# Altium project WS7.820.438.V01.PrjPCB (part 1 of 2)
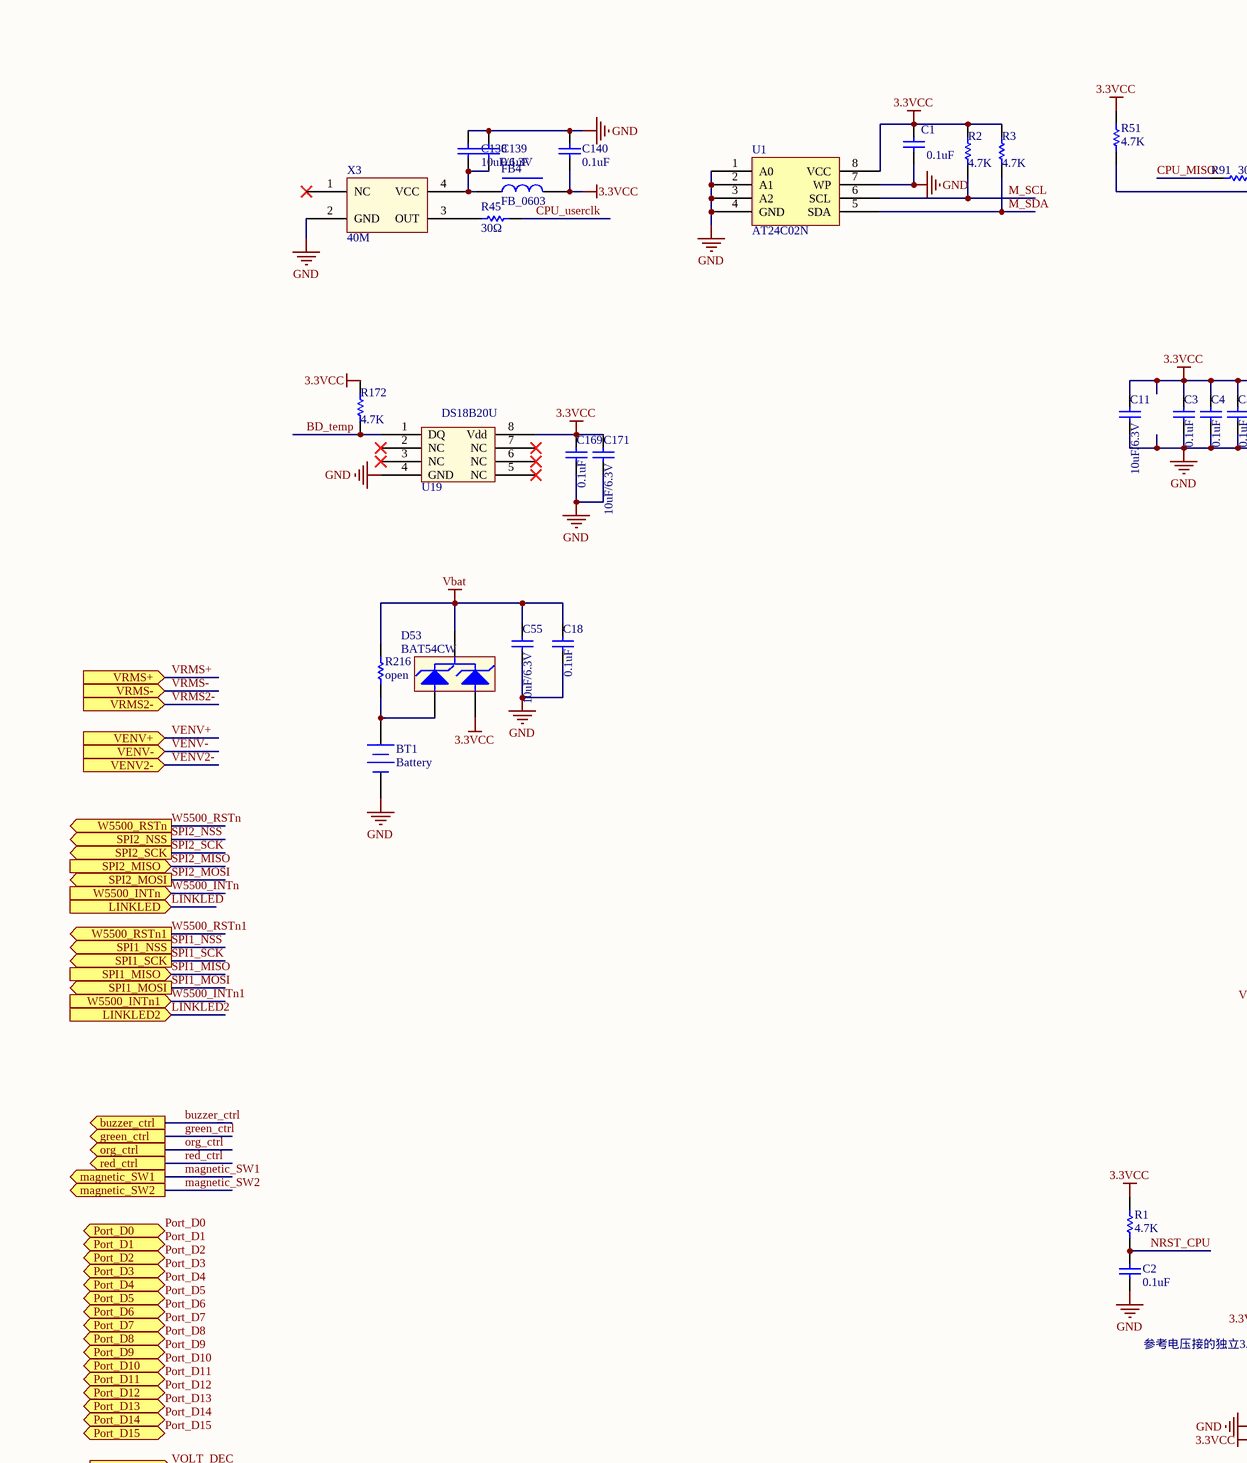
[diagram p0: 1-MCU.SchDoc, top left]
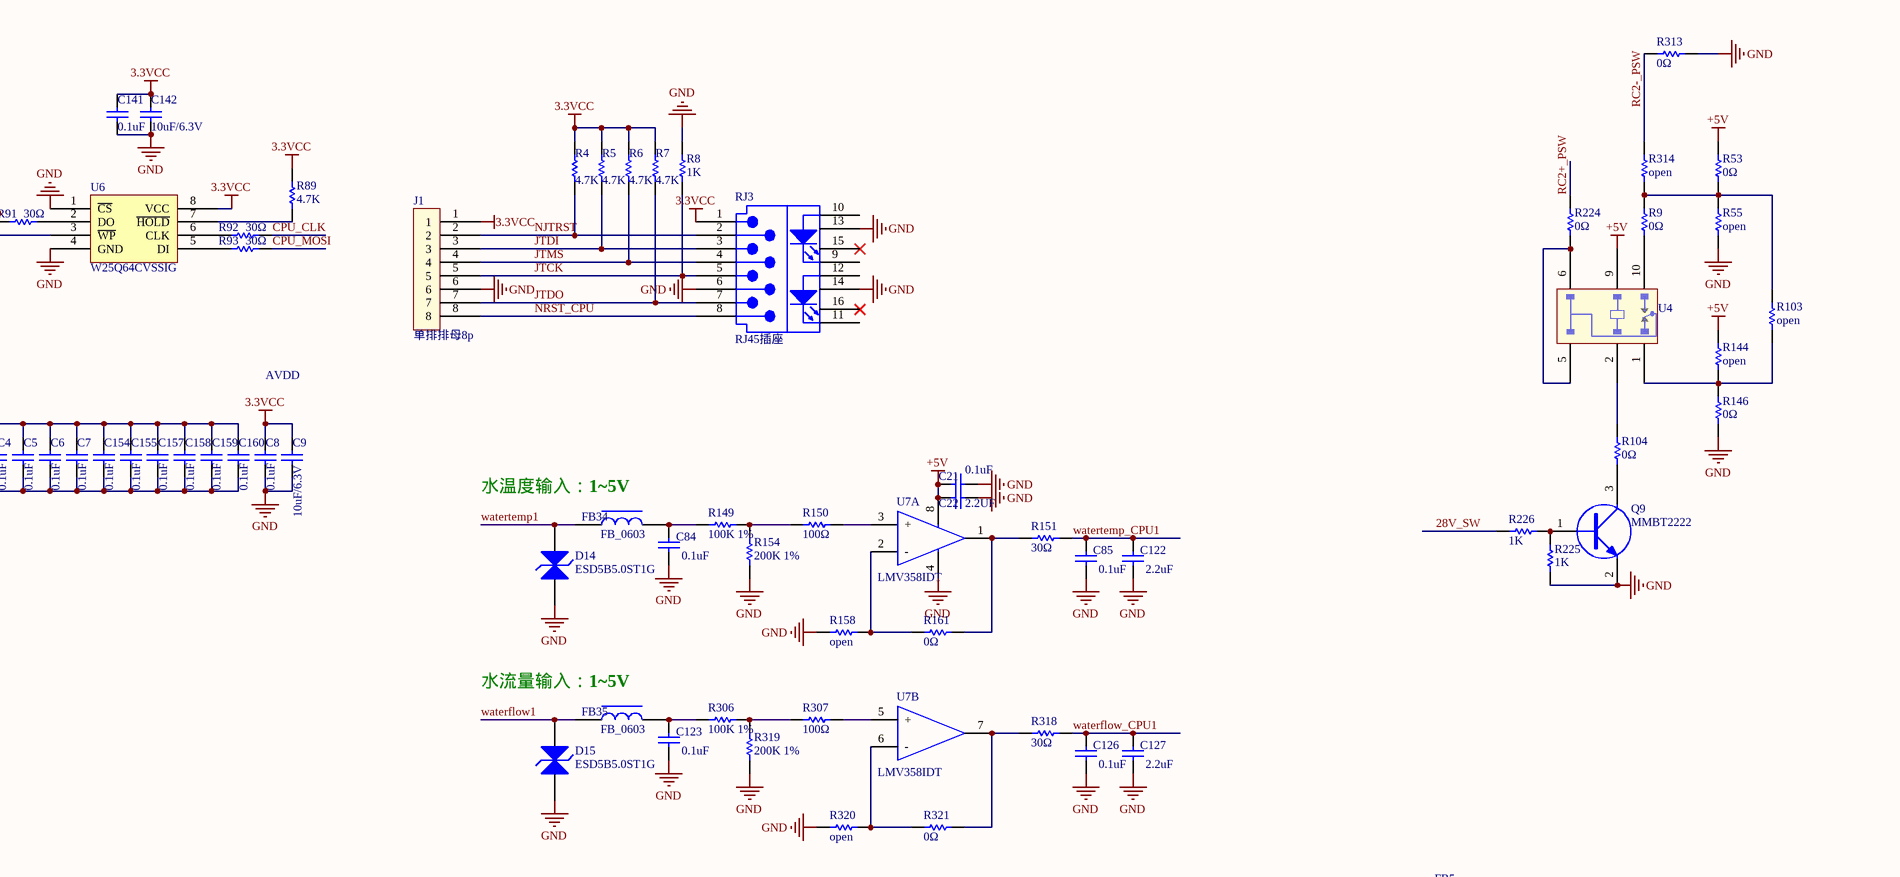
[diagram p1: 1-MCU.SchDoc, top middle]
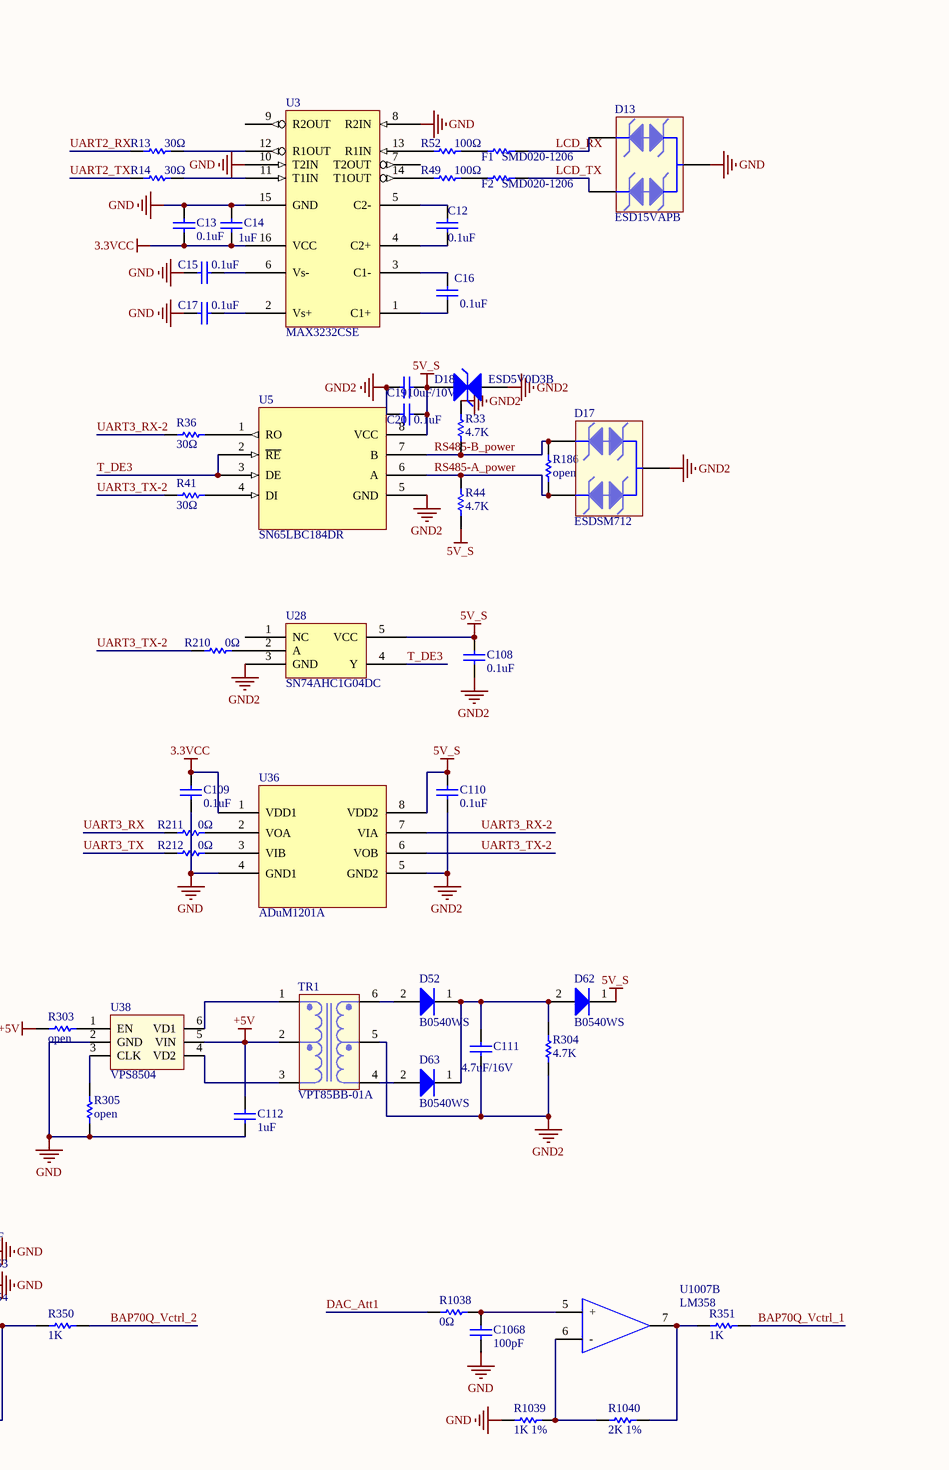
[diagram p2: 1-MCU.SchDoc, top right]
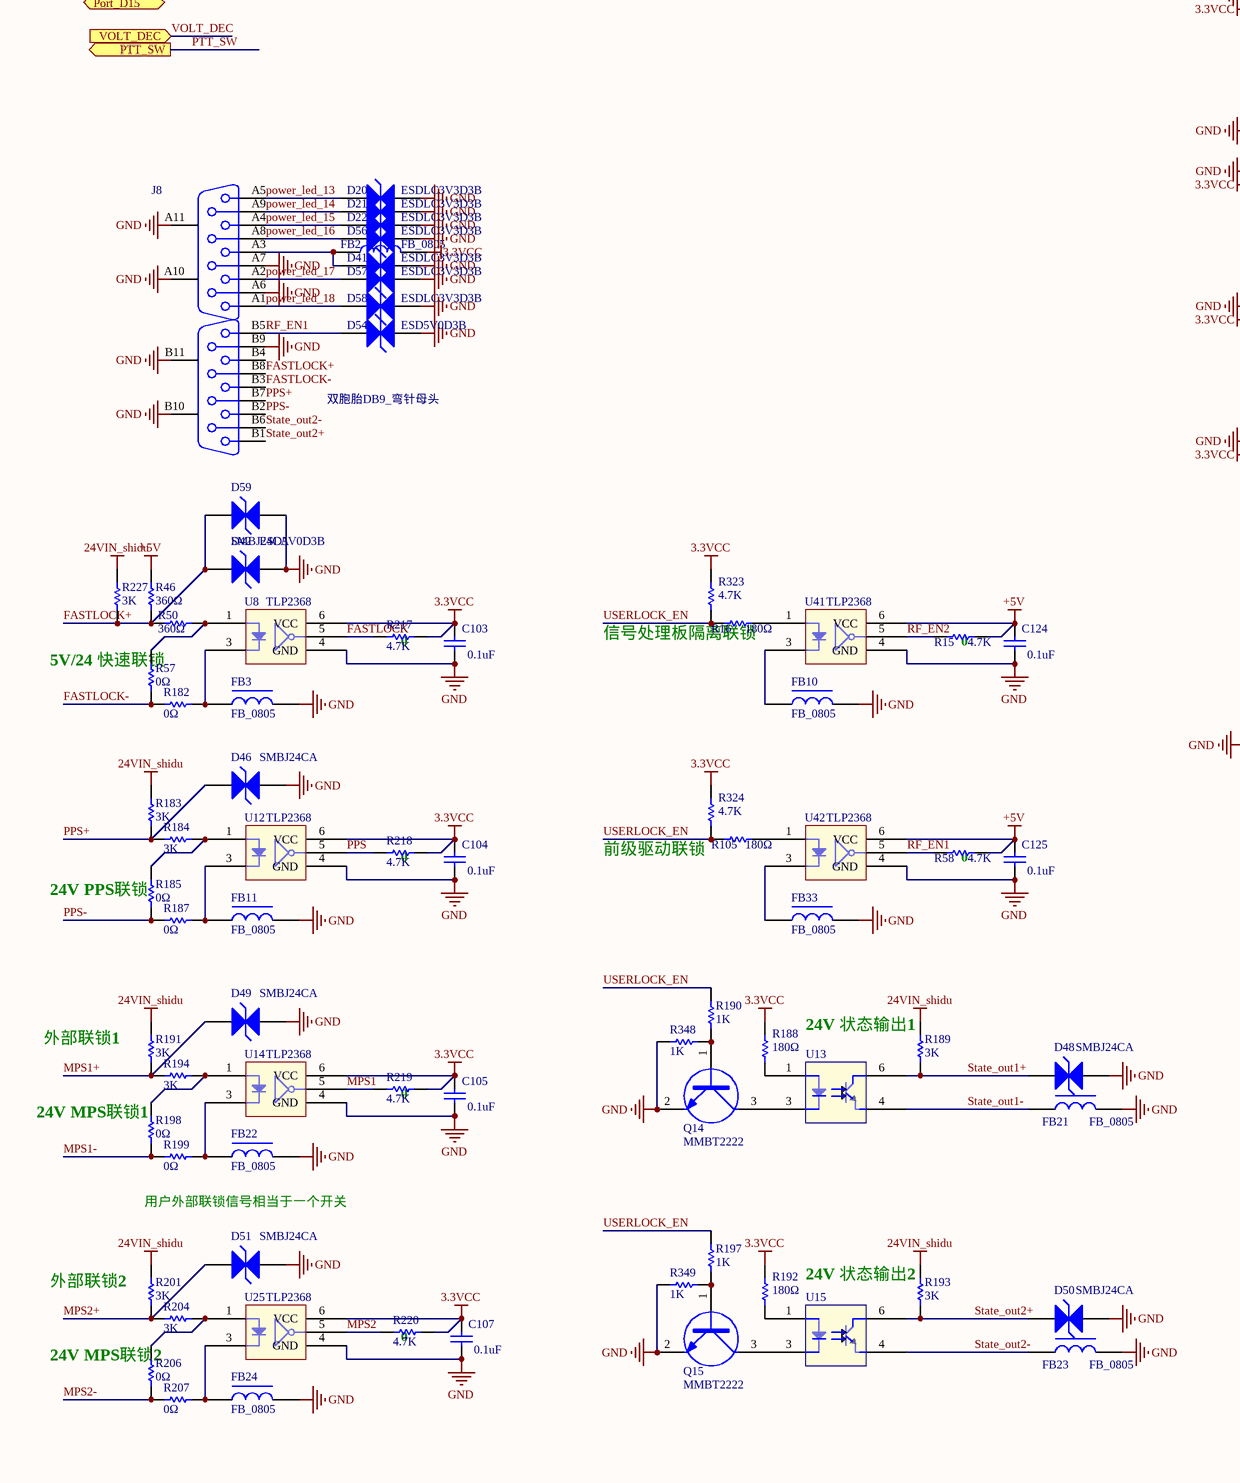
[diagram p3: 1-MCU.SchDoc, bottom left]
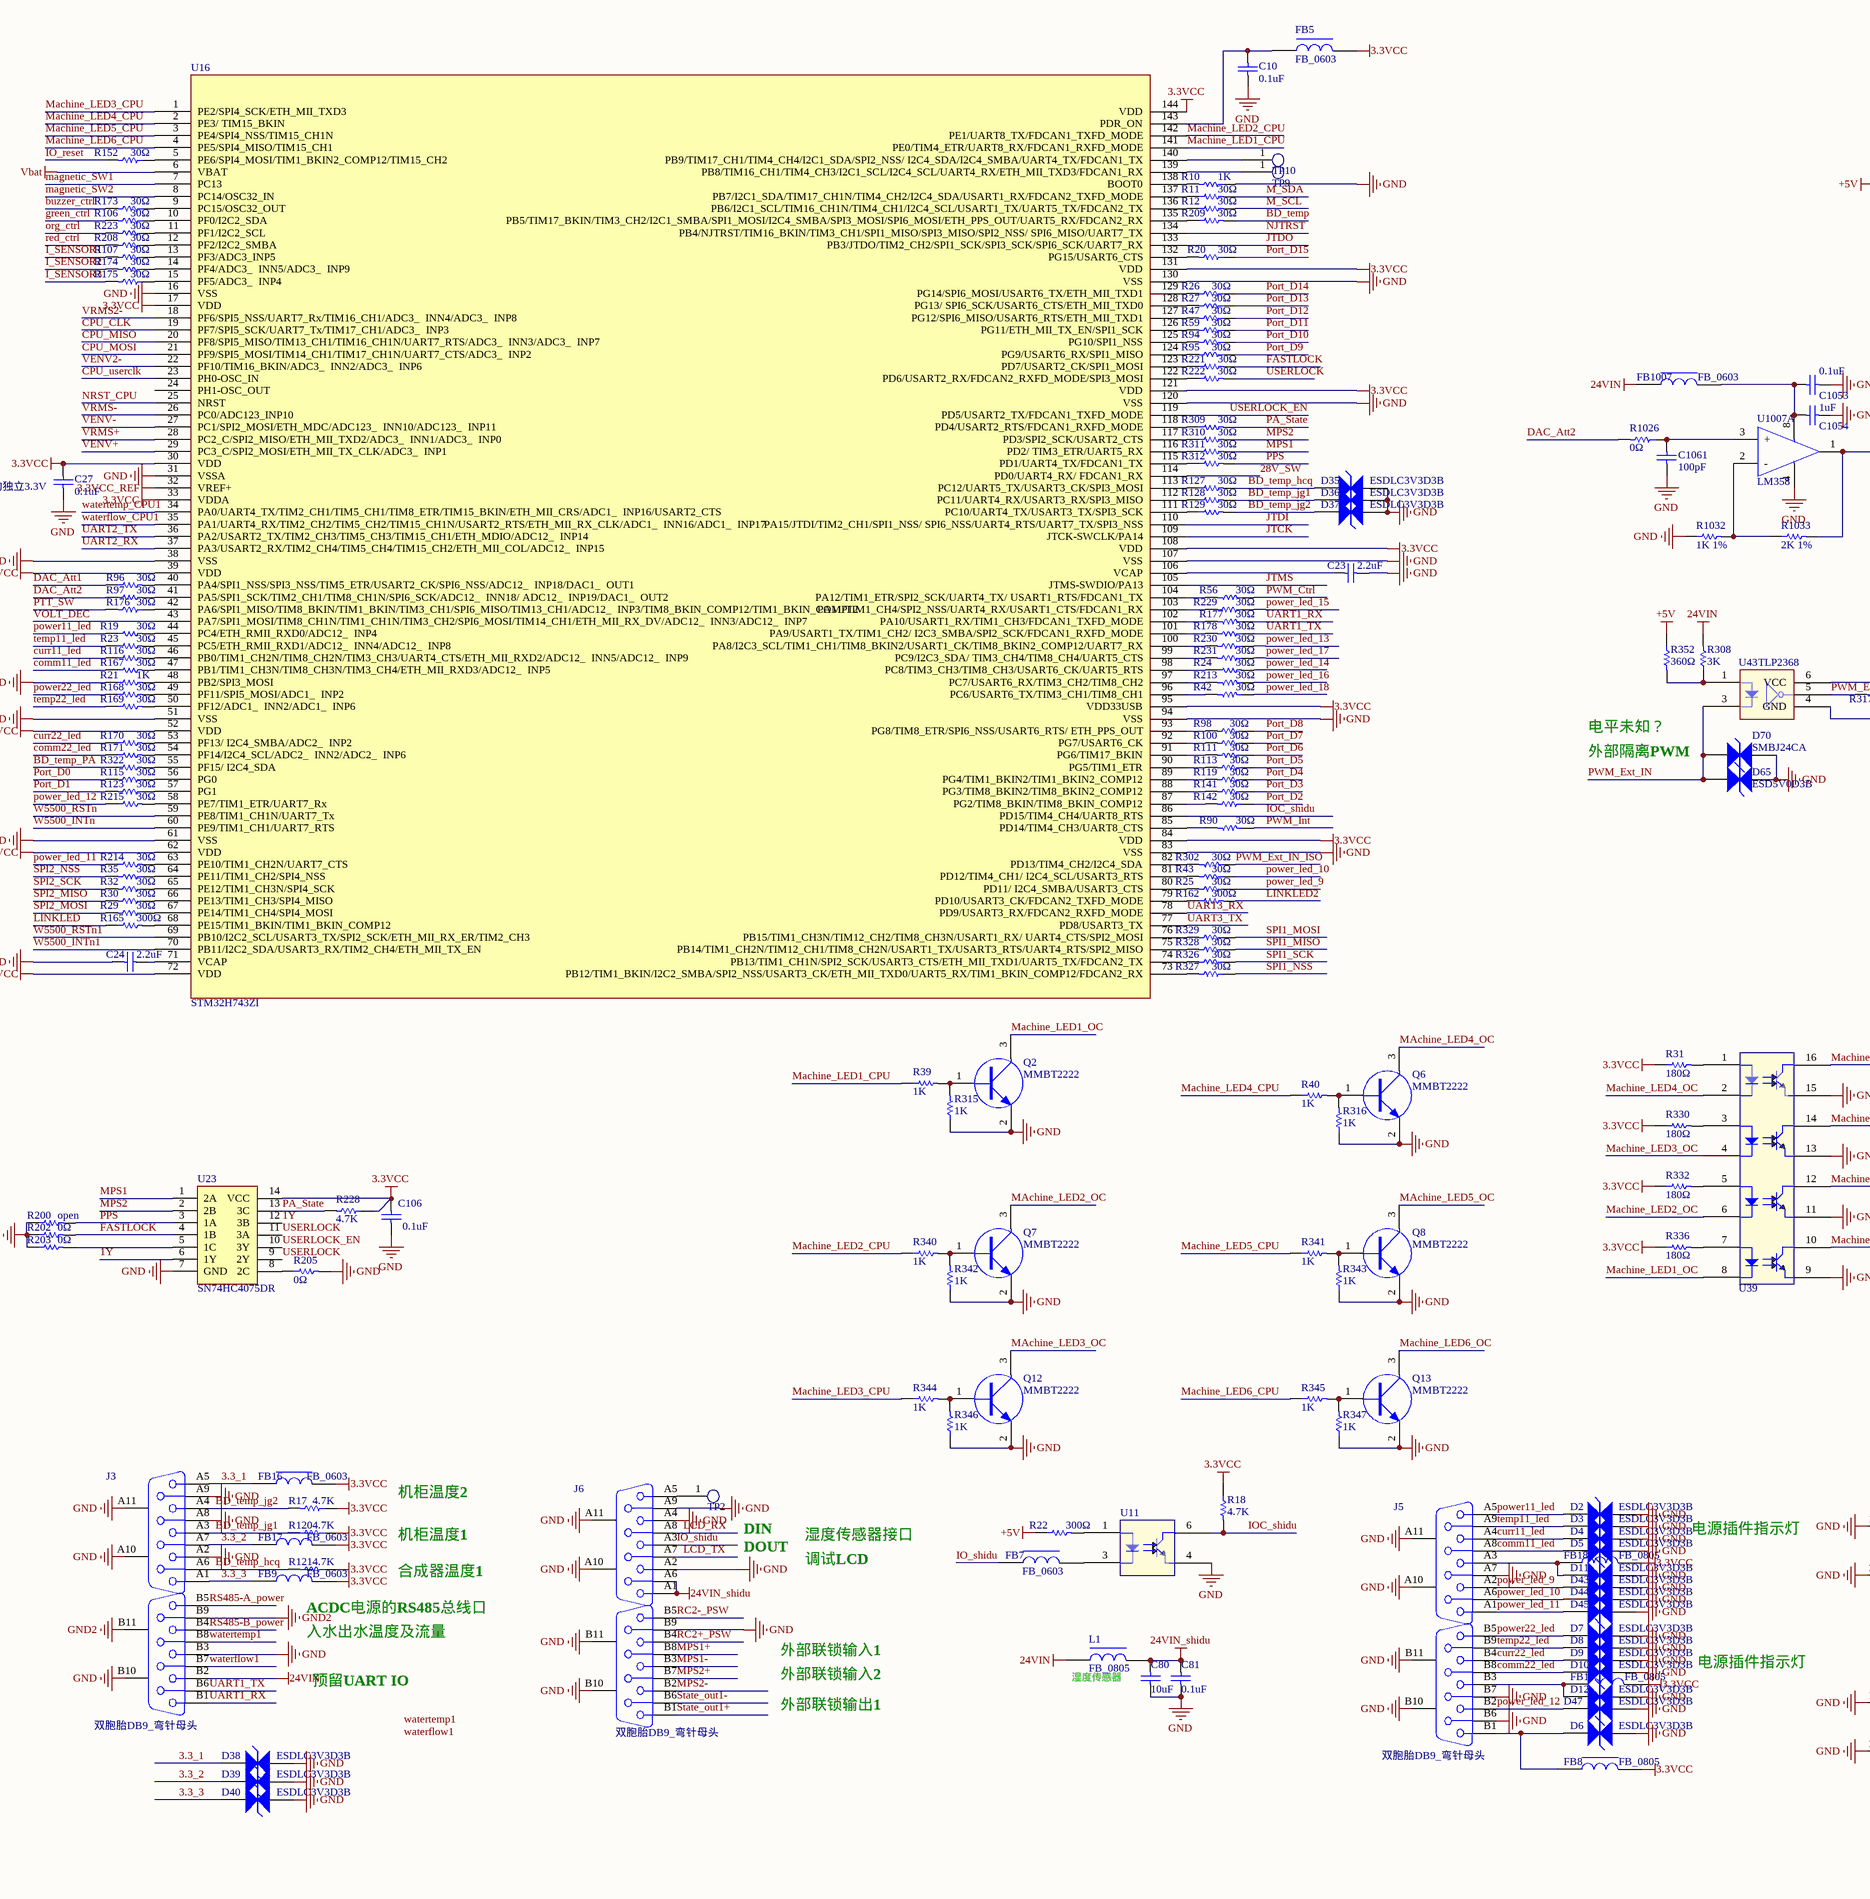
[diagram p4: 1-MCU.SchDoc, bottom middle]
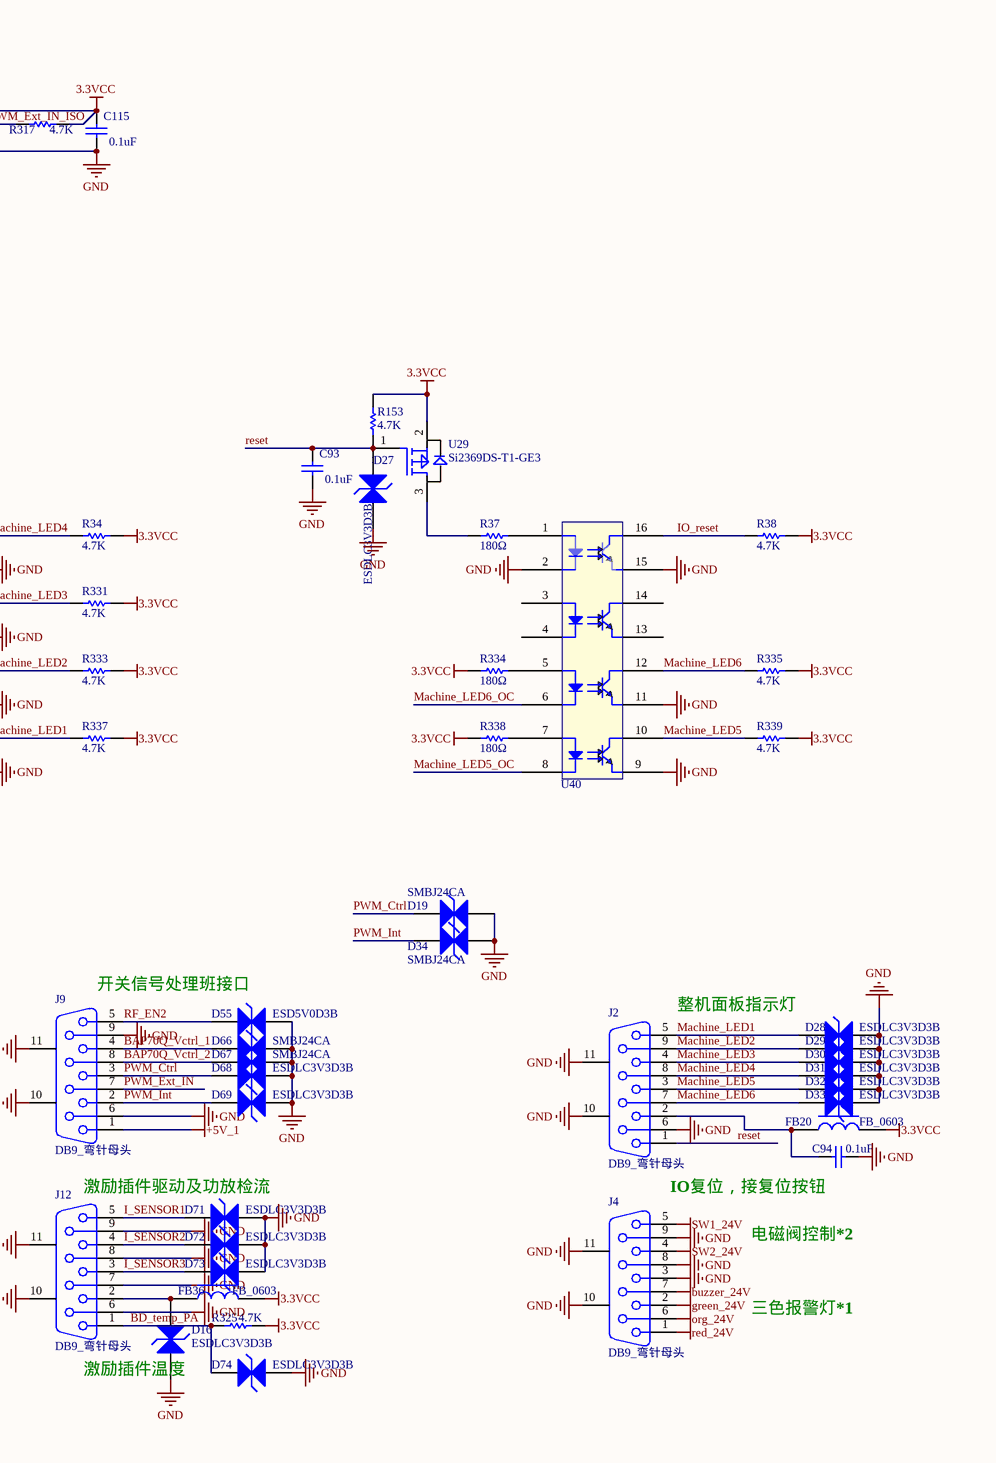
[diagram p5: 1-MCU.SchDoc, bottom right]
5 sheets, 863 parts. Net scope: flat (ports and power ports of the same name join across sheets).
Board file: WS7.820.438.V01.PcbDoc
Sheets:
  1-MCU.SchDoc
  2-RJ45.SchDoc
  3-ADC.SchDoc
  4-RF-PD.SchDoc
  5-POWER.SchDoc

## Sheet 1-MCU.SchDoc
size A1

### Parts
BT1  Battery  [CR2032]
C1  0.1uF  [C0603]
C2  0.1uF  [C0603]
C3  0.1uF  [C0603]
C4  0.1uF  [C0603]
C5  0.1uF  [C0603]
C6  0.1uF  [C0603]
C7  0.1uF  [C0603]
C8  0.1uF  [C0603]
C9  10uF/6.3V  [C0603]
C10  0.1uF  [C0603]
C11  10uF/6.3V  [C0603]
C12  0.1uF  [C0603]
C13  0.1uF  [C0603]
C14  1uF  [C0603]
C15  0.1uF  [C0603]
C16  0.1uF  [C0603]
C17  0.1uF  [C0603]
C18  0.1uF  [C0603]
C19  10uF/10V  [C0805]
C20  0.1uF  [C0603]
C21  0.1uF  [C0603]
C22  2.2UF  [C0603]
C23  2.2uF  [C0603]
C24  2.2uF  [C0603]
C27  0.1uF  [C0603]
C55  10uF/6.3V  [C0603]
C80  10uF  [C1210]
C81  0.1uF  [C0603]
C84  0.1uF  [C0603]
C85  0.1uF  [C0603]
C93  0.1uF  [C0603]
C94  0.1uF  [C0603]
C103  0.1uF  [C0603]
C104  0.1uF  [C0603]
C105  0.1uF  [C0603]
C106  0.1uF  [C0603]
C107  0.1uF  [C0603]
C108  0.1uF  [C0603]
C109  0.1uF  [C0603]
C110  0.1uF  [C0603]
C111  4.7uF/16V  [C0603]
C112  1uF  [C0603]
C115  0.1uF  [C0603]
C122  2.2uF  [C0603]
C123  0.1uF  [C0603]
C124  0.1uF  [C0603]
C125  0.1uF  [C0603]
C126  0.1uF  [C0603]
C127  2.2uF  [C0603]
C138  10uF/6.3V  [C0603]
C139  0.1uF  [C0603]
C140  0.1uF  [C0603]
C141  0.1uF  [C0603]
C142  10uF/6.3V  [C0603]
C154  0.1uF  [C0603]
C155  0.1uF  [C0603]
C157  0.1uF  [C0603]
C158  0.1uF  [C0603]
C159  0.1uF  [C0603]
C160  0.1uF  [C0603]
C169  0.1uF  [C0603]
C171  10uF/6.3V  [C0603]
C1053  0.1uF  [C0603]
C1054  1uF  [C0603]
C1061  100pF  [C0603]
C1068  100pF  [C0603]
D2  ESDLC3V3D3B  [SOD-323]
D3  ESDLC3V3D3B  [SOD-323]
D4  ESDLC3V3D3B  [SOD-323]
D5  ESDLC3V3D3B  [SOD-323]
D6  ESDLC3V3D3B  [SOD-323]
D7  ESDLC3V3D3B  [SOD-323]
D8  ESDLC3V3D3B  [SOD-323]
D9  ESDLC3V3D3B  [SOD-323]
D10  ESDLC3V3D3B  [SOD-323]
D11  ESDLC3V3D3B  [SOD-323]
D12  ESDLC3V3D3B  [SOD-323]
D13  ESD15VAPB  [SOT23-3]
D14  ESD5B5.0ST1G  [SOD-523]
D15  ESD5B5.0ST1G  [SOD-523]
D16  ESDLC3V3D3B  [SOD-323]
D17  ESDSM712  [SOT23-3]
D18  ESD5V0D3B  [SOD-323]
D19  SMBJ24CA  [DO-214AA]  (no BOM)
D20  ESDLC3V3D3B  [SOD-323]
D21  ESDLC3V3D3B  [SOD-323]
D22  ESDLC3V3D3B  [SOD-323]
D27  ESDLC3V3D3B  [SOD-323]
D28  ESDLC3V3D3B  [SOD-323]
D29  ESDLC3V3D3B  [SOD-323]
D30  ESDLC3V3D3B  [SOD-323]
D31  ESDLC3V3D3B  [SOD-323]
D32  ESDLC3V3D3B  [SOD-323]
D33  ESDLC3V3D3B  [SOD-323]
D34  SMBJ24CA  [DO-214AA]  (no BOM)
D35  ESDLC3V3D3B  [SOD-323]
D36  ESDLC3V3D3B  [SOD-323]
D37  ESDLC3V3D3B  [SOD-323]
D38  ESDLC3V3D3B  [SOD-323]
D39  ESDLC3V3D3B  [SOD-323]
D40  ESDLC3V3D3B  [SOD-323]
D41  ESDLC3V3D3B  [SOD-323]
D42  ESD5V0D3B  [SOD-323]
D43  ESDLC3V3D3B  [SOD-323]
D44  ESDLC3V3D3B  [SOD-323]
D45  ESDLC3V3D3B  [SOD-323]
D46  SMBJ24CA  [DO-214AA]
D47  ESDLC3V3D3B  [SOD-323]
D48  SMBJ24CA  [DO-214AA]
D49  SMBJ24CA  [DO-214AA]
D50  SMBJ24CA  [DO-214AA]
D51  SMBJ24CA  [DO-214AA]
D52  B0540WS  [SOD-323]
D53  BAT54CW  [SOT-323]
D54  ESD5V0D3B  [SOD-323]
D55  ESD5V0D3B  [SOD-323]
D56  ESDLC3V3D3B  [SOD-323]
D57  ESDLC3V3D3B  [SOD-323]
D58  ESDLC3V3D3B  [SOD-323]
D59  SMBJ24CA  [DO-214AA]  (no BOM)
D62  B0540WS  [SOD-323]
D63  B0540WS  [SOD-323]
D65  ESD5V0D3B  [SOD-323]
D66  SMBJ24CA  [DO-214AA]
D67  SMBJ24CA  [DO-214AA]
D68  ESDLC3V3D3B  [SOD-323]
D69  ESDLC3V3D3B  [SOD-323]
D70  SMBJ24CA  [DO-214AA]  (no BOM)
D71  ESDLC3V3D3B  [SOD-323]
D72  ESDLC3V3D3B  [SOD-323]
D73  ESDLC3V3D3B  [SOD-323]
D74  ESDLC3V3D3B  [SOD-323]
F1  SMD020-1206  [R1206]
F2  SMD020-1206  [R1206]
FB2  FB_0805  [L0805]
FB3  FB_0805  [L0805]
FB4  FB_0603  [L0603]
FB5  FB_0603  [L0603]
FB7  FB_0603  [L0603]
FB8  FB_0805  [L0805]
FB9  FB_0603  [L0603]
FB10  FB_0805  [L0805]
FB11  FB_0805  [L0805]
FB16  FB_0603  [L0603]
FB17  FB_0603  [L0603]
FB18  FB_0805  [L0805]
FB19  FB_0805  [L0805]
FB20  FB_0603  [L0603]
FB21  FB_0805  [L0805]
FB22  FB_0805  [L0805]
FB23  FB_0805  [L0805]
FB24  FB_0805  [L0805]
FB33  FB_0805  [L0805]
FB34  FB_0603  [L0603]
FB35  FB_0603  [L0603]
FB36  FB_0603  [L0603]
FB1007  FB_0603  [L0603]
J1  单排排母8p  [SIP8TM-2R54]
J2  DB9_弯针母头  [DB9TM-RF]
J3  双胞胎DB9_弯针母头  [DB9TM-RF-双胞胎]
J4  DB9_弯针母头  [DB9TM-RF]
J5  双胞胎DB9_弯针母头  [DB9TM-RF-双胞胎]
J6  双胞胎DB9_弯针母头  [DB9TM-RF-双胞胎]
J8  双胞胎DB9_弯针母头  [DB9TM-RF-双胞胎]
J9  DB9_弯针母头  [DB9TM-RF]
J12  DB9_弯针母头  [DB9TM-RF]
L1  FB_0805  [L0805]
Q2  MMBT2222  [SOT23-3]
Q6  MMBT2222  [SOT23-3]
Q7  MMBT2222  [SOT23-3]
Q8  MMBT2222  [SOT23-3]
Q9  MMBT2222  [SOT23-3]
Q12  MMBT2222  [SOT23-3]
Q13  MMBT2222  [SOT23-3]
Q14  MMBT2222  [SOT23-3]
Q15  MMBT2222  [SOT23-3]
R1  4.7K  [R0603]
R2  4.7K  [R0603]
R3  4.7K  [R0603]
R4  4.7K  [R0603]
R5  4.7K  [R0603]
R6  4.7K  [R0603]
R7  4.7K  [R0603]
R8  1K  [R0603]
R9  0Ω  [R0603]
R10  1K  [R0603]
R11  30Ω  [R0603]
R12  30Ω  [R0603]
R13  30Ω  [R0603]
R14  30Ω  [R0603]
R15  4.7K  [R0603]
R16  180Ω  [R0603]
R17  4.7K  [R0603]
R18  4.7K  [R0603]
R19  30Ω  [R0603]
R20  30Ω  [R0603]
R21  1K  [R0603]
R22  300Ω  [R0603]
R23  30Ω  [R0603]
R24  30Ω  [R0603]
R25  30Ω  [R0603]
R26  30Ω  [R0603]
R27  30Ω  [R0603]
R29  30Ω  [R0603]
R30  30Ω  [R0603]
R31  180Ω  [R0603]
R32  30Ω  [R0603]
R33  4.7K  [R0603]
R34  4.7K  [R0603]
R35  30Ω  [R0603]
R36  30Ω  [R0603]
R37  180Ω  [R0603]
R38  4.7K  [R0603]
R39  1K  [R0603]
R40  1K  [R0603]
R41  30Ω  [R0603]
R42  30Ω  [R0603]
R43  30Ω  [R0603]
R44  4.7K  [R0603]
R45  30Ω  [R0603]
R46  360Ω  [R0603]
R47  30Ω  [R0603]
R49  100Ω  [R0603]
R50  360Ω  [R1206]  (no BOM)
R51  4.7K  [R0603]
R52  100Ω  [R0603]
R53  0Ω  [R0603]
R55  open  [R0603]  (no BOM)
R56  30Ω  [R0603]
R57  0Ω  [R0603]
R58  4.7K  [R0603]
R59  30Ω  [R0603]
R89  4.7K  [R0603]
R90  30Ω  [R0603]
R91  30Ω  [R0603]
R92  30Ω  [R0603]
R93  30Ω  [R0603]
R94  30Ω  [R0603]
R95  30Ω  [R0603]
R96  30Ω  [R0603]
R97  30Ω  [R0603]
R98  30Ω  [R0603]
R100  30Ω  [R0603]
R103  open  [R0603]  (no BOM)
R104  0Ω  [R0603]
R105  180Ω  [R0603]
R106  30Ω  [R0603]
R107  30Ω  [R0603]
R111  30Ω  [R0603]
R113  30Ω  [R0603]
R115  30Ω  [R0603]
R116  30Ω  [R0603]
R119  30Ω  [R0603]
R120  4.7K  [R0603]
R121  4.7K  [R0603]
R123  30Ω  [R0603]
R127  30Ω  [R0603]
R128  30Ω  [R0603]
R129  30Ω  [R0603]
R141  30Ω  [R0603]
R142  30Ω  [R0603]
R144  open  [R0603]  (no BOM)
R146  0Ω  [R0603]
R149  100K 1%  [R0603]
R150  100Ω  [R0603]
R151  30Ω  [R0603]
R152  30Ω  [R0603]
R153  4.7K  [R0603]
R154  200K 1%  [R0603]
R158  open  [R0603]  (no BOM)
R161  0Ω  [R0603]
R162  300Ω  [R0603]
R165  300Ω  [R0603]
R167  30Ω  [R0603]
R168  30Ω  [R0603]
R169  30Ω  [R0603]
R170  30Ω  [R0603]
R171  30Ω  [R0603]
R172  4.7K  [R0603]
R173  30Ω  [R0603]
R174  30Ω  [R0603]
R175  30Ω  [R0603]
R176  30Ω  [R0603]
R177  30Ω  [R0603]
R178  30Ω  [R0603]
R182  0Ω  [R0603]  (no BOM)
R183  3K  [R1206]
R184  3K  [R1206]  (no BOM)
R185  0Ω  [R0603]
R186  open  [R0603]  (no BOM)
R187  0Ω  [R0603]  (no BOM)
R188  180Ω  [R0603]
R189  3K  [R1206]
R190  1K  [R0603]
R191  3K  [R1206]
R192  180Ω  [R0603]
R193  3K  [R1206]
R194  3K  [R1206]  (no BOM)
R197  1K  [R0603]
R198  0Ω  [R0603]
R199  0Ω  [R0603]  (no BOM)
R200  open  [R0603]  (no BOM)
R201  3K  [R1206]
R202  0Ω  [R0603]
R203  0Ω  [R0603]
R204  3K  [R1206]  (no BOM)
R205  0Ω  [R0603]
R206  0Ω  [R0603]
R207  0Ω  [R0603]  (no BOM)
R208  30Ω  [R0603]
R209  30Ω  [R0603]
R210  0Ω  [R0603]
R211  0Ω  [R0603]
R212  0Ω  [R0603]
R213  30Ω  [R0603]
R214  30Ω  [R0603]
R215  30Ω  [R0603]
R216  open  [R0603]  (no BOM)
R217  4.7K  [R0603]
R218  4.7K  [R0603]
R219  4.7K  [R0603]
R220  4.7K  [R0603]
R221  30Ω  [R0603]
R222  30Ω  [R0603]
R223  30Ω  [R0603]
R224  0Ω  [R0603]
R225  1K  [R0603]
R226  1K  [R0603]
R227  3K  [R1206]  (no BOM)
R228  4.7K  [R0603]
R229  30Ω  [R0603]
R230  30Ω  [R0603]
R231  30Ω  [R0603]
R302  30Ω  [R0603]
R303  open  [R0603]  (no BOM)
R304  4.7K  [R0603]
R305  open  [R0603]  (no BOM)
R306  100K 1%  [R0603]
R307  100Ω  [R0603]
R308  3K  [R1206]  (no BOM)
R309  30Ω  [R0603]
R310  30Ω  [R0603]
R311  30Ω  [R0603]
R312  30Ω  [R0603]
R313  0Ω  [R0603]
R314  open  [R0603]  (no BOM)
R315  1K  [R0603]
R316  1K  [R0603]
R317  4.7K  [R0603]
R318  30Ω  [R0603]
R319  200K 1%  [R0603]
R320  open  [R0603]  (no BOM)
R321  0Ω  [R0603]
R322  30Ω  [R0603]
R323  4.7K  [R0603]
R324  4.7K  [R0603]
R325  4.7K  [R0603]
R326  30Ω  [R0603]
R327  30Ω  [R0603]
R328  30Ω  [R0603]
R329  30Ω  [R0603]
R330  180Ω  [R0603]
R331  4.7K  [R0603]
R332  180Ω  [R0603]
R333  4.7K  [R0603]
R334  180Ω  [R0603]
R335  4.7K  [R0603]
R336  180Ω  [R0603]
R337  4.7K  [R0603]
R338  180Ω  [R0603]
R339  4.7K  [R0603]
R340  1K  [R0603]
R341  1K  [R0603]
R342  1K  [R0603]
R343  1K  [R0603]
R344  1K  [R0603]
R345  1K  [R0603]
R346  1K  [R0603]
R347  1K  [R0603]
R348  1K  [R0603]
R349  1K  [R0603]
R350  1K  [R0603]
R351  1K  [R0603]
R352  360Ω  [R0603]
R1026  0Ω  [R0603]
R1032  1K 1%  [R0603]
R1033  2K 1%  [R0603]
R1038  0Ω  [R0603]
R1039  1K 1%  [R0603]
R1040  2K 1%  [R0603]
RJ3  RJ45插座  [RJ45TH-1x1-2R54-LED]
TP2  TEST  [TP0R8]  (value not drawn)  (no BOM)
TP9  TEST  [TP0R8]  (value not drawn)  (no BOM)
TP10  TEST  [TP0R8]  (value not drawn)  (no BOM)
TR1  VPT85BB-01A  [VPT85BB-01A-6SM-2R54-6R65X7R45]
U1  AT24C02N  [SOIC8_1R27_3R9x4R9]
U3  MAX3232CSE  [SOIC16-1R27-3R9x9R9]
U4  G5V-1-5VDC  [G5V-1-5VDC]  (value not drawn)
U5  SN65LBC184DR  [SOIC8_1R27_3R9x4R9]
U6  W25Q64CVSSIG  [SOIC8_1R27_5R3x5R3]
U7  LMV358IDT  [SOIC8_1R27_3R9x4R9]  (parts A,B of 2)
U8  TLP2368  [SO6-1R27-4R55X3R7]
U11  TLP181  [TLP181]  (value not drawn)
U12  TLP2368  [SO6-1R27-4R55X3R7]
U13  TLP181  [TLP181]  (value not drawn)
U14  TLP2368  [SO6-1R27-4R55X3R7]
U15  TLP181  [TLP181]  (value not drawn)
U16  STM32H743ZI  [LQFP144_0R5_20x20]
U19  DS18B20U  [TSSOP8-0R65-3R0x3R0]
U23  SN74HC4075DR  [SOIC14-1R27-3R9x8R65]
U25  TLP2368  [SO6-1R27-4R55X3R7]
U28  SN74AHC1G04DC  [SC70-5-1R3x2R2]
U29  Si2369DS-T1-GE3  [SOT23-3]
U36  ADuM1201A  [SOIC8_1R27_3R9x4R9]
U38  VPS8504  [SOT23-6]
U39  LTV-247  [SOIC16-1R27-3R9x9R9]  (value not drawn)
U40  LTV-247  [SOIC16-1R27-3R9x9R9]  (value not drawn)
U41  TLP2368  [SO6-1R27-4R55X3R7]
U42  TLP2368  [SO6-1R27-4R55X3R7]
U43  TLP2368  [SO6-1R27-4R55X3R7]
U1007  LM358  [SOIC8_1R27_3R9x4R9]  (parts A,B of 2)
X3  40M  [CRY4SM-5R0x7R0]

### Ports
buzzer_ctrl (out), green_ctrl (out), LINKLED2 (in), LINKLED (in), magnetic_SW1 (out), magnetic_SW2 (out), org_ctrl (out), Port_D0 (bidir), Port_D1 (bidir), Port_D2 (bidir), Port_D3 (bidir), Port_D4 (bidir), Port_D5 (bidir), Port_D6 (bidir), Port_D7 (bidir), Port_D8 (bidir), Port_D9 (bidir), Port_D10 (bidir), Port_D11 (bidir), Port_D12 (bidir), Port_D13 (bidir), Port_D14 (bidir), Port_D15 (bidir), PTT_SW (out), red_ctrl (out), SPI1_MISO (in), SPI1_MOSI (out), SPI1_NSS (out), SPI1_SCK (out), SPI2_MISO (in), SPI2_MOSI (out), SPI2_NSS (out), SPI2_SCK (out), VENV2- (in), VENV+ (in), VENV- (in), VOLT_DEC (in), VRMS2- (in), VRMS+ (in), VRMS- (in), W5500_INTn1 (in), W5500_INTn (in), W5500_RSTn1 (out), W5500_RSTn (out)

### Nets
3.3VCC: C1.2 C3.2 C4.2 C5.2 C6.2 C7.2 C8.2 C9.2 C11.2 C13.2 C14.1 C27.2 C103.2 C104.2 C105.2 C106.2 C107.2 C109.2 C115.2 C140.1 C141.2 C142.2 C154.2 C155.2 C157.2 C158.2 C159.2 C160.2 C169.2 C171.2 D53.2 FB2.2 FB4.2 FB5.2 FB8.2 FB9.2 FB16.2 FB17.2 FB18.2 FB19.2 FB20.2 FB36.2 J1.1 R1.2 R2.2 R3.2 R4.2 R5.2 R6.2 R7.2 R17.1 R18.1 R31.1 R34.1 R38.1 R51.1 R89.1 R120.1 R121.1 R153.2 R172.2 R188.1 R192.1 R217.1 R218.1 R219.1 R220.1 R228.1 R317.1 R323.1 R324.1 R325.1 R330.1 R331.1 R332.1 R333.1 R334.1 R335.1 R336.1 R337.1 R338.1 R339.1 RJ3.1(TX+) U1.8(VCC) U3.16(VCC) U6.8(VCC) U8.6(VCC) U12.6(VCC) U14.6(VCC) U16.17(VDD) U16.30(VDD) U16.33(VDDA) U16.39(VDD) U16.52(VDD) U16.62(VDD) U16.72(VDD) U16.84(VDD) U16.95(VDD33USB) U16.108(VDD) U16.121(VDD) U16.131(VDD) U16.144(VDD) U19.8(Vdd) U23.14(VCC) U25.6(VCC) U29.2(S) U36.1(VDD1) U43.6(VCC)
3.3VCC_REF: U16.32(VREF+)
5V_S: C19.2 C20.2 C108.2 C110.2 D18.1 D62.1(K) R44.1 U5.8(VCC) U28.5(VCC) U36.8(VDD2)
24VIN: FB1007.1 J3.B2 L1.1 R308.2
24VIN_shidu: C80.2 C81.2 J6.A1 J6.A6 L1.2 R183.2 R189.2 R191.2 R193.2 R201.2 R227.2
+5V: C21.2 C22.1 C112.2 C124.2 C125.2 R15.1 R22.1 R46.2 R53.2 R58.1 R144.2 R303.1 R352.1 TR1.2 U4.9 U7.8 U38.5(VIN) U41.6(VCC) U42.6(VCC)
+5V_1: J9.1
buzzer_24V: J4.7
GND: BT1.2(-) C1.1 C2.1 C3.1 C4.1 C5.1 C6.1 C7.1 C8.1 C9.1 C10.2 C11.1 C13.1 C14.2 C15.2 C17.2 C18.1 C21.1 C22.2 C23.1 C24.2 C27.1 C55.1 C80.1 C81.1 C84.1 C85.1 C93.1 C94.2 C103.1 C104.1 C105.1 C106.1 C107.1 C109.1 C112.1 C115.1 C122.1 C123.1 C124.1 C125.1 C126.1 C127.1 C138.1 C139.2 C140.2 C141.1 C142.1 C154.1 C155.1 C157.1 C158.1 C159.1 C160.1 C169.1 C171.1 C1053.1 C1054.2 C1061.1 C1068.1 D2.2 D3.2 D4.2 D5.2 D6.2 D7.2 D8.2 D9.2 D10.2 D11.2 D12.2 D13.3 D14.1 D15.1 D16.2 D19.1 D20.2 D21.2 D22.2 D27.2 D28.2 D29.2 D30.2 D31.2 D32.2 D33.2 D34.1 D35.2 D36.2 D37.2 D38.2 D39.2 D40.2 D41.2 D42.2 D43.2 D44.2 D45.2 D46.1 D47.2 D48.1 D49.1 D50.1 D51.1 D54.2 D55.2 D56.2 D57.2 D58.2 D59.1 D65.2 D66.1 D67.1 D68.2 D69.2 D70.1 D71.2 D72.2 D73.2 D74.2 FB3.2 FB10.2 FB11.2 FB21.2 FB22.2 FB23.2 FB24.2 FB33.2 J1.6 J2.6 J2.10 J2.11 J3.A2 J3.A8 J3.A9 J3.A10 J3.A11 J3.B3 J3.B10 J4.3 J4.8 J4.9 J4.10 J4.11 J5.A7 J5.A10 J5.A11 J5.B6 J5.B7 J5.B10 J5.B11 J6.A2 J6.A4 J6.A9 J6.A10 J6.A11 J6.B9 J6.B10 J6.B11 J8.A6 J8.A7 J8.A10 J8.A11 J8.B9 J8.B10 J8.B11 J9.6 J9.9 J9.10 J9.11 J12.6 J12.7 J12.8 J12.9 J12.10 J12.11 Q2.2(E) Q6.2(E) Q7.2(E) Q8.2(E) Q9.2(E) Q12.2(E) Q13.2(E) Q14.2(E) Q15.2(E) R8.1 R10.1 R21.1 R55.1 R146.1 R154.1 R158.1 R200.1 R202.1 R203.1 R205.2 R225.1 R305.1 R313.2 R315.1 R316.1 R319.1 R320.1 R342.1 R343.1 R346.1 R347.1 R348.1 R349.1 R1032.1 R1039.1 RJ3.6(RX-) RJ3.13 RJ3.14 U1.1(A0) U1.2(A1) U1.3(A2) U1.4(GND) U1.7(WP) U3.8(R2IN) U3.10(T2IN) U3.15(GND) U6.1(~{CS}) U6.4(GND) U7.4 U8.4(GND) U11.4 U12.4(GND) U14.4(GND) U16.16(VSS) U16.31(VSSA) U16.38(VSS) U16.51(VSS) U16.61(VSS) U16.83(VSS) U16.94(VSS) U16.107(VSS) U16.120(VSS) U16.130(VSS) U19.4(GND) U23.7(GND) U25.4(GND) U36.4(GND1) U38.2(GND) U39.9 U39.11 U39.13 U39.15 U40.2 U40.9 U40.11 U40.15 U41.4(GND) U42.4(GND) U43.4(GND) U1007.4 X3.2(GND)
GND2: C19.1 C20.1 C108.1 C110.1 C111.1 D17.3 D18.2 J3.B9 J3.B11 R33.2 R304.1 TR1.5 U5.5(GND) U28.3(GND) U36.5(GND2)
green_24V: J4.2
org_24V: J4.6
red_24V: J4.1
SW1_24V: J4.5
SW2_24V: J4.4
Vbat: C18.2 C55.2 D53.3 R216.2 U16.6(VBAT)
1Y: U23.6(1Y) U23.12(3B)
3.3_1: D38.1 FB16.1 J3.A5
3.3_2: D39.1 FB17.1 J3.A7
3.3_3: D40.1 FB9.1 J3.A1
28V_SW: R226.1 U16.114(PD0/UART4_RX/_FDCAN1_RX)
BAP70Q_Vctrl_1: D66.2 J9.4 R351.2
BAP70Q_Vctrl_2: D67.2 J9.8 R350.2
BD_temp: R172.1 R209.2 U19.1(DQ)
BD_temp_hcq: D35.1 J3.A6 R121.2 R127.2
BD_temp_jg1: D36.1 J3.A3 R120.2 R128.2
BD_temp_jg2: D37.1 J3.A4 R17.2 R129.2
BD_temp_PA: D74.1 J12.1 R322.1 R325.2
buzzer_ctrl: R173.2 ; port buzzer_ctrl
comm11_led: D5.1 J5.A8 R167.1
comm22_led: D10.1 J5.B8 R171.1
CPU_CLK: R92.2 U16.19(PF7/SPI5_SCK/UART7_Tx/TIM17_CH1/ADC3___INP3)
CPU_MISO: R91.1 U16.20(PF8/SPI5_MISO/TIM13_CH1/TIM16_CH1N/UART7_RTS/ADC3___INN3/ADC3___INP7)
CPU_MOSI: R93.2 U16.21(PF9/SPI5_MOSI/TIM14_CH1/TIM17_CH1N/UART7_CTS/ADC3___INP2)
CPU_userclk: R45.2 U16.23(PH0-OSC_IN)
curr11_led: D4.1 J5.A4 R116.1
curr22_led: D9.1 J5.B4 R170.1
DAC_Att1: R96.1 R1038.2
DAC_Att2: R97.1 R1026.2
FASTLOCK: R202.2 R217.2 R221.2 U8.5(Vo) U23.4(1B)
FASTLOCK+: D42.1 D59.2 J8.B8 R46.1 R50.2 R227.1
FASTLOCK-: J8.B3 R57.2 R182.2
green_ctrl: R106.2 ; port green_ctrl
I_SENSOR1: D71.1 J12.5 R107.2
I_SENSOR2: D72.1 J12.4 R174.2
I_SENSOR3: D73.1 J12.3 R175.2
IO_reset: R38.2 R152.2 U40.16
IO_shidu: FB7.1 J6.A3
IOC_shidu: R18.2 U11.6 U16.86(PD15/TIM4_CH4/UART8_RTS)
JTCK: J1.5 R8.2 RJ3.5(NC) U16.109(JTCK-SWCLK/PA14)
JTDI: J1.3 R5.1 RJ3.3(RX+) U16.110(PA15/JTDI/TIM2_CH1/SPI1_NSS/_SPI6_NSS/UART4_RTS/UART7_TX/SPI3_NSS)
JTDO: J1.7 R7.1 RJ3.7(NC) U16.133(PB3/JTDO/TIM2_CH2/SPI1_SCK/SPI3_SCK/SPI6_SCK/UART7_RX)
JTMS: J1.4 R6.1 RJ3.4(NC) U16.105(JTMS-SWDIO/PA13)
LCD_RX: D13.2 F1.2 J6.A8
LCD_TX: D13.1 F2.2 J6.A7
LINKLED: R165.1 ; port LINKLED
LINKLED2: R162.2 ; port LINKLED2
M_SCL: R2.1 R12.2 U1.6(SCL)
M_SDA: R3.1 R11.2 U1.5(SDA)
Machine_LED1: D28.1 J2.5 R337.2 U39.10
Machine_LED1_CPU: R39.1 U16.141(PE0/TIM4_ETR/UART8_RX/FDCAN1_RXFD_MODE)
Machine_LED1_OC: Q2.3(C) U39.8
Machine_LED2: D29.1 J2.9 R333.2 U39.12
Machine_LED2_CPU: R340.1 U16.142(PE1/UART8_TX/FDCAN1_TXFD_MODE)
Machine_LED2_OC: Q7.3(C) U39.6
Machine_LED3: D30.1 J2.4 R331.2 U39.14
Machine_LED3_CPU: R344.1 U16.1(PE2/SPI4_SCK/ETH_MII_TXD3)
Machine_LED3_OC: Q12.3(C) U39.4
Machine_LED4: D31.1 J2.8 R34.2 U39.16
Machine_LED4_CPU: R40.1 U16.2(PE3/_TIM15_BKIN)
Machine_LED4_OC: Q6.3(C) U39.2
Machine_LED5: D32.1 J2.3 R339.2 U40.10
Machine_LED5_CPU: R341.1 U16.3(PE4/SPI4_NSS/TIM15_CH1N)
Machine_LED5_OC: Q8.3(C) U40.8
Machine_LED6: D33.1 J2.7 R335.2 U40.12
Machine_LED6_CPU: R345.1 U16.4(PE5/SPI4_MISO/TIM15_CH1)
Machine_LED6_OC: Q13.3(C) U40.6
magnetic_SW1: U16.7(PC13) ; port magnetic_SW1
magnetic_SW2: U16.8(PC14/OSC32_IN) ; port magnetic_SW2
MPS1: R219.2 R311.2 U14.5(Vo) U23.1(2A)
MPS1+: D49.2 J6.B8 R191.1 R194.2
MPS1-: J6.B3 R198.2 R199.2
MPS2: R220.2 R310.2 U23.2(2B) U25.5(Vo)
MPS2+: D51.2 J6.B7 R201.1 R204.2
MPS2-: J6.B2 R206.2 R207.2
NJTRST: J1.2 R4.1 RJ3.2(TX-) U16.134(PB4/NJTRST/TIM16_BKIN/TIM3_CH1/SPI1_MISO/SPI3_MISO/SPI2_NSS/_SPI6_MISO/UART7_TX)
NRST_CPU: C2.2 J1.8 R1.1 RJ3.8(NC) U16.25(NRST)
org_ctrl: R223.2 ; port org_ctrl
PA_State: R228.2 R309.2 U23.13(3C)
Port_D0: R115.2 ; port Port_D0
Port_D1: R123.2 ; port Port_D1
Port_D2: R142.1 ; port Port_D2
Port_D3: R141.1 ; port Port_D3
Port_D4: R119.1 ; port Port_D4
Port_D5: R113.1 ; port Port_D5
Port_D6: R111.1 ; port Port_D6
Port_D7: R100.1 ; port Port_D7
Port_D8: R98.1 ; port Port_D8
Port_D9: R95.1 ; port Port_D9
Port_D10: R94.1 ; port Port_D10
Port_D11: R59.1 ; port Port_D11
Port_D12: R47.1 ; port Port_D12
Port_D13: R27.1 ; port Port_D13
Port_D14: R26.1 ; port Port_D14
Port_D15: R20.1 ; port Port_D15
power11_led: D2.1 J5.A5 R19.1
power22_led: D7.1 J5.B5 R168.1
power_led_9: D43.1 J5.A2 R25.1
power_led_10: D44.1 J5.A6 R43.1
power_led_11: D45.1 J5.A1 R214.1
power_led_12: D47.1 J5.B2 R215.1
power_led_13: D20.1 J8.A5 R230.1
power_led_14: D21.1 J8.A9 R24.2
power_led_15: D22.1 J8.A4 R229.1
power_led_16: D56.1 J8.A8 R213.1
power_led_17: D57.1 J8.A2 R231.1
power_led_18: D58.1 J8.A1 R42.1
PPS: R200.2 R218.2 R312.2 U12.5(Vo) U23.3(1A)
PPS+: D46.2 J8.B7 R183.1 R184.2
PPS-: J8.B2 R185.2 R187.2
PTT_SW: R176.2 ; port PTT_SW
PWM_Ctrl: D19.2 D68.1 J9.3 R56.1
PWM_Ext_IN: D65.1 D70.2 J9.7 U43.3(Cathode)
PWM_Ext_IN_ISO: R302.1 R317.2 U43.5(Vo)
PWM_Int: D34.2 D69.1 J9.2 R90.1
RC2+_PSW: J6.B4 R224.1
RC2-_PSW: J6.B5 R313.1 R314.1
red_ctrl: R208.2 ; port red_ctrl
reset: C93.2 D27.1 J2.1 R153.1 U29.1(G)
RF_EN1: D54.1 J8.B5 R58.2 U42.5(Vo)
RF_EN2: D55.1 J9.5 R15.2 U41.5(Vo)
RS485-A_power: D17.1 J3.B5 R44.2 R186.2 U5.6(A)
RS485-B_power: D17.2 J3.B4 R33.1 R186.1 U5.7(B)
SPI1_MISO: R328.1 ; port SPI1_MISO
SPI1_MOSI: R329.1 ; port SPI1_MOSI
SPI1_NSS: R327.1 ; port SPI1_NSS
SPI1_SCK: R326.1 ; port SPI1_SCK
SPI2_MISO: R30.2 ; port SPI2_MISO
SPI2_MOSI: R29.2 ; port SPI2_MOSI
SPI2_NSS: R35.2 ; port SPI2_NSS
SPI2_SCK: R32.2 ; port SPI2_SCK
State_out1+: D48.2 J6.B1 R189.1 U13.6
State_out1-: FB21.1 J6.B6 U13.4
State_out2+: D50.2 J8.B1 R193.1 U15.6
State_out2-: FB23.1 J8.B6 U15.4
T_DE3: U5.2(~{RE}) U5.3(DE) U28.4(Y)
temp11_led: D3.1 J5.A9 R23.1
temp22_led: D8.1 J5.B9 R169.1
UART1_RX: J3.B1 R177.1
UART1_TX: J3.B6 R178.1
UART2_RX: R13.1 U16.37(PA3/USART2_RX/TIM2_CH4/TIM5_CH4/TIM15_CH2/ETH_MII_COL/ADC12___INP15)
UART2_TX: R14.1 U16.36(PA2/USART2_TX/TIM2_CH3/TIM5_CH3/TIM15_CH1/ETH_MDIO/ADC12___INP14)
UART3_RX: R211.1 U16.78(PD9/USART3_RX/FDCAN2_RXFD_MODE)
UART3_RX-2: R36.1 U36.7(VIA)
UART3_TX: R212.1 U16.77(PD8/USART3_TX)
UART3_TX-2: R41.1 R210.1 U36.6(VOB)
USERLOCK: R222.2 U23.9(2Y) U23.11(3A)
USERLOCK_EN: R16.1 R105.1 R190.1 R197.1 R323.2 R324.2 U16.119(PD5/USART2_TX/FDCAN1_TXFD_MODE) U23.10(3Y)
VENV2-: U16.22(PF10/TIM16_BKIN/ADC3___INN2/ADC3___INP6) ; port VENV2-
VENV+: U16.29(PC3_C/SPI2_MOSI/ETH_MII_TX_CLK/ADC3___INP1) ; port VENV+
VENV-: U16.27(PC1/SPI2_MOSI/ETH_MDC/ADC123___INN10/ADC123___INP11) ; port VENV-
VOLT_DEC: U16.43(PA7/SPI1_MOSI/TIM8_CH1N/TIM1_CH1N/TIM3_CH2/SPI6_MOSI/TIM14_CH1/ETH_MII_RX_DV/ADC12___INN3/ADC12___INP7) ; port VOLT_DEC
VRMS2-: U16.18(PF6/SPI5_NSS/UART7_Rx/TIM16_CH1/ADC3___INN4/ADC3___INP8) ; port VRMS2-
VRMS+: U16.28(PC2_C/SPI2_MISO/ETH_MII_TXD2/ADC3___INN1/ADC3___INP0) ; port VRMS+
VRMS-: U16.26(PC0/ADC123_INP10) ; port VRMS-
W5500_INTn: U16.60(PE9/TIM1_CH1/UART7_RTS) ; port W5500_INTn
W5500_INTn1: U16.70(PB11/I2C2_SDA/USART3_RX/TIM2_CH4/ETH_MII_TX_EN) ; port W5500_INTn1
W5500_RSTn: U16.59(PE8/TIM1_CH1N/UART7_Tx) ; port W5500_RSTn
W5500_RSTn1: U16.69(PB10/I2C2_SCL/USART3_TX/SPI2_SCK/ETH_MII_RX_ER/TIM2_CH3) ; port W5500_RSTn1
waterflow1: D15.2 FB35.1 J3.B7
waterflow_CPU1: C126.2 C127.2 R318.2 U16.35(PA1/UART4_RX/TIM2_CH2/TIM5_CH2/TIM15_CH1N/USART2_RTS/ETH_MII_RX_CLK/ADC1___INN16/ADC1___INP17)
watertemp1: D14.2 FB34.1 J3.B8
watertemp_CPU1: C85.2 C122.2 R151.2 U16.34(PA0/UART4_TX/TIM2_CH1/TIM5_CH1/TIM8_ETR/TIM15_BKIN/ETH_MII_CRS/ADC1___INP16/USART2_CTS)
NetBT1_1: BT1.1(+) D53.1 R216.1
NetC10_1: C10.1 FB5.1 U16.143(PDR_ON)
NetC12_1: C12.1 U3.4(C2+)
NetC12_2: C12.2 U3.5(C2-)
NetC15_1: C15.1 U3.6(Vs-)
NetC16_1: C16.1 U3.1(C1+)
NetC16_2: C16.2 U3.3(C1-)
NetC17_1: C17.1 U3.2(Vs+)
NetC23_2: C23.2 U16.106(VCAP)
NetC24_1: C24.1 U16.71(VCAP)
NetC84_2: C84.2 FB34.2 R149.1
NetC94_1: C94.1 FB20.1 J2.2
NetC111_2: C111.2 D52.1(K) D62.2(A) D63.1(K) R304.2
NetC123_2: C123.2 FB35.2 R306.1
NetC138_2: C138.2 C139.1 FB4.1 X3.4(VCC)
NetC1053_2: C1053.2 C1054.1 FB1007.2 U1007.8
NetC1061_2: C1061.2 R1026.1 U1007.3(+)
NetC1068_2: C1068.2 R1038.1 U1007.5(+)
NetD6_1: D6.1 FB8.1 J5.B1
NetD11_1: D11.1 FB18.1 J5.A3
NetD12_1: D12.1 FB19.1 J5.B3
NetD16_1: D16.1 FB36.1 J12.2
NetD41_1: D41.1 FB2.1 J8.A3
NetD52_2: D52.2(A) TR1.6
NetD63_2: D63.2(A) TR1.4
NetF1_1: F1.1 R52.2
NetF2_1: F2.1 R49.2
NetFB3_1: FB3.1 R182.1 U8.3(Cathode)
NetFB7_2: FB7.2 U11.3
NetFB10_1: FB10.1 U41.3(Cathode)
NetFB11_1: FB11.1 R187.1 U12.3(Cathode)
NetFB22_1: FB22.1 R199.1 U14.3(Cathode)
NetFB24_1: FB24.1 R207.1 U25.3(Cathode)
NetFB33_1: FB33.1 U42.3(Cathode)
NetJ6_A5: J6.A5 TP2.1(TP)
NetQ2_1: Q2.1(B) R39.2 R315.2
NetQ6_1: Q6.1(B) R40.2 R316.2
NetQ7_1: Q7.1(B) R340.2 R342.2
NetQ8_1: Q8.1(B) R341.2 R343.2
NetQ9_1: Q9.1(B) R225.2 R226.2
NetQ9_3: Q9.3(C) R104.2
NetQ12_1: Q12.1(B) R344.2 R346.2
NetQ13_1: Q13.1(B) R345.2 R347.2
NetQ14_1: Q14.1(B) R190.2 R348.2
NetQ14_3: Q14.3(C) U13.3
NetQ15_1: Q15.1(B) R197.2 R349.2
NetQ15_3: Q15.3(C) U15.3
NetR9_1: R9.1 R53.1 R55.2 R103.2 R314.2
NetR9_2: R9.2 U4.10
NetR10_2: R10.2 U16.138(BOOT0)
NetR11_1: R11.1 U16.137(PB7/I2C1_SDA/TIM17_CH1N/TIM4_CH2/I2C4_SDA/USART1_RX/FDCAN2_TXFD_MODE)
NetR12_1: R12.1 U16.136(PB6/I2C1_SCL/TIM16_CH1N/TIM4_CH1/I2C4_SCL/USART1_TX/UART5_TX/FDCAN2_TX)
NetR13_2: R13.2 U3.12(R1OUT)
NetR14_2: R14.2 U3.11(T1IN)
NetR16_2: R16.2 U41.1(Anode)
NetR19_2: R19.2 U16.44(PC4/ETH_RMII_RXD0/ADC12___INP4)
NetR20_2: R20.2 U16.132(PG15/USART6_CTS)
NetR21_2: R21.2 U16.48(PB2/SPI3_MOSI)
NetR22_2: R22.2 U11.1
NetR23_2: R23.2 U16.45(PC5/ETH_RMII_RXD1/ADC12___INN4/ADC12___INP8)
NetR24_1: R24.1 U16.98(PC8/TIM3_CH3/TIM8_CH3/USART6_CK/UART5_RTS)
NetR25_2: R25.2 U16.80(PD11/_I2C4_SMBA/USART3_CTS)
NetR26_2: R26.2 U16.129(PG14/SPI6_MOSI/USART6_TX/ETH_MII_TXD1)
NetR27_2: R27.2 U16.128(PG13/_SPI6_SCK/USART6_CTS/ETH_MII_TXD0)
NetR29_1: R29.1 U16.67(PE14/TIM1_CH4/SPI4_MOSI)
NetR30_1: R30.1 U16.66(PE13/TIM1_CH3/SPI4_MISO)
NetR31_2: R31.2 U39.1
NetR32_1: R32.1 U16.65(PE12/TIM1_CH3N/SPI4_SCK)
NetR35_1: R35.1 U16.64(PE11/TIM1_CH2/SPI4_NSS)
NetR36_2: R36.2 U5.1(RO)
NetR37_1: R37.1 U29.3(D)
NetR37_2: R37.2 U40.1
NetR41_2: R41.2 U5.4(DI)
NetR42_2: R42.2 U16.96(PC6/USART6_TX/TIM3_CH1/TIM8_CH1)
NetR43_2: R43.2 U16.81(PD12/TIM4_CH1/_I2C4_SCL/USART3_RTS)
NetR45_1: R45.1 X3.3(OUT)
NetR47_2: R47.2 U16.127(PG12/SPI6_MISO/USART6_RTS/ETH_MII_TXD1)
NetR49_1: R49.1 U3.14(T1OUT)
NetR50_1: R50.1 R57.1 U8.1(Anode)
NetR51_2: R51.2 U6.3(~{WP})
NetR52_1: R52.1 U3.13(R1IN)
NetR56_2: R56.2 U16.104(PA12/TIM1_ETR/SPI2_SCK/UART4_TX/_USART1_RTS/FDCAN1_TX)
NetR59_2: R59.2 U16.126(PG11/ETH_MII_TX_EN/SPI1_SCK)
NetR89_2: R89.2 U6.7(~{HOLD})
NetR90_2: R90.2 U16.85(PD14/TIM4_CH3/UART8_CTS)
NetR91_2: R91.2 U6.2(DO)
NetR92_1: R92.1 U6.6(CLK)
NetR93_1: R93.1 U6.5(DI)
NetR94_2: R94.2 U16.125(PG10/SPI1_NSS)
NetR95_2: R95.2 U16.124(PG9/USART6_RX/SPI1_MISO)
NetR96_2: R96.2 U16.40(PA4/SPI1_NSS/SPI3_NSS/TIM5_ETR/USART2_CK/SPI6_NSS/ADC12___INP18/DAC1___OUT1)
NetR97_2: R97.2 U16.41(PA5/SPI1_SCK/TIM2_CH1/TIM8_CH1N/SPI6_SCK/ADC12___INN18/_ADC12___INP19/DAC1___OUT2)
NetR98_2: R98.2 U16.93(PG8/TIM8_ETR/SPI6_NSS/USART6_RTS/_ETH_PPS_OUT)
NetR100_2: R100.2 U16.92(PG7/USART6_CK)
NetR103_1: R103.1 R144.1 R146.2 U4.1
NetR104_1: R104.1 U4.2
NetR105_2: R105.2 U42.1(Anode)
NetR106_1: R106.1 U16.10(PF0/I2C2_SDA)
NetR107_1: R107.1 U16.13(PF3/ADC3_INP5)
NetR111_2: R111.2 U16.91(PG6/TIM17_BKIN)
NetR113_2: R113.2 U16.90(PG5/TIM1_ETR)
NetR115_1: R115.1 U16.56(PG0)
NetR116_2: R116.2 U16.46(PB0/TIM1_CH2N/TIM8_CH2N/TIM3_CH3/UART4_CTS/ETH_MII_RXD2/ADC12___INN5/ADC12___INP9)
NetR119_2: R119.2 U16.89(PG4/TIM1_BKIN2/TIM1_BKIN2_COMP12)
NetR123_1: R123.1 U16.57(PG1)
NetR127_1: R127.1 U16.113(PC12/UART5_TX/USART3_CK/SPI3_MOSI)
NetR128_1: R128.1 U16.112(PC11/UART4_RX/USART3_RX/SPI3_MISO)
NetR129_1: R129.1 U16.111(PC10/UART4_TX/USART3_TX/SPI3_SCK)
NetR141_2: R141.2 U16.88(PG3/TIM8_BKIN2/TIM8_BKIN2_COMP12)
NetR142_2: R142.2 U16.87(PG2/TIM8_BKIN/TIM8_BKIN_COMP12)
NetR149_2: R149.2 R150.1 R154.2
NetR150_2: R150.2 U7.3(+)
NetR151_1: R151.1 R161.2 U7.1
NetR152_1: R152.1 U16.5(PE6/SPI4_MOSI/TIM1_BKIN2_COMP12/TIM15_CH2)
NetR158_2: R158.2 R161.1 U7.2(-)
NetR162_1: R162.1 U16.79(PD10/USART3_CK/FDCAN2_TXFD_MODE)
NetR165_2: R165.2 U16.68(PE15/TIM1_BKIN/TIM1_BKIN_COMP12)
NetR167_2: R167.2 U16.47(PB1/TIM1_CH3N/TIM8_CH3N/TIM3_CH4/ETH_MII_RXD3/ADC12___INP5)
NetR168_2: R168.2 U16.49(PF11/SPI5_MOSI/ADC1___INP2)
NetR169_2: R169.2 U16.50(PF12/ADC1___INN2/ADC1___INP6)
NetR170_2: R170.2 U16.53(PF13/_I2C4_SMBA/ADC2___INP2)
NetR171_2: R171.2 U16.54(PF14/I2C4_SCL/ADC2___INN2/ADC2___INP6)
NetR173_1: R173.1 U16.9(PC15/OSC32_OUT)
NetR174_1: R174.1 U16.14(PF4/ADC3___INN5/ADC3___INP9)
NetR175_1: R175.1 U16.15(PF5/ADC3___INP4)
NetR176_1: R176.1 U16.42(PA6/SPI1_MISO/TIM8_BKIN/TIM1_BKIN/TIM3_CH1/SPI6_MISO/TIM13_CH1/ADC12___INP3/TIM8_BKIN_COMP12/TIM1_BKIN_COMP12)
NetR177_2: R177.2 U16.102(PA10/USART1_RX/TIM1_CH3/FDCAN1_TXFD_MODE)
NetR178_2: R178.2 U16.101(PA9/USART1_TX/TIM1_CH2/_I2C3_SMBA/SPI2_SCK/FDCAN1_RXFD_MODE)
NetR184_1: R184.1 R185.1 U12.1(Anode)
NetR188_2: R188.2 U13.1
NetR192_2: R192.2 U15.1
NetR194_1: R194.1 R198.1 U14.1(Anode)
NetR203_2: R203.2 U23.5(1C)
NetR204_1: R204.1 R206.1 U25.1(Anode)
NetR205_1: R205.1 U23.8(2C)
NetR208_1: R208.1 U16.12(PF2/I2C2_SMBA)
NetR209_1: R209.1 U16.135(PB5/TIM17_BKIN/TIM3_CH2/I2C1_SMBA/SPI1_MOSI/I2C4_SMBA/SPI3_MOSI/SPI6_MOSI/ETH_PPS_OUT/UART5_RX/FDCAN2_RX)
NetR210_2: R210.2 U28.2(A)
NetR211_2: R211.2 U36.2(VOA)
NetR212_2: R212.2 U36.3(VIB)
NetR213_2: R213.2 U16.97(PC7/USART6_RX/TIM3_CH2/TIM8_CH2)
NetR214_2: R214.2 U16.63(PE10/TIM1_CH2N/UART7_CTS)
NetR215_2: R215.2 U16.58(PE7/TIM1_ETR/UART7_Rx)
NetR221_1: R221.1 U16.123(PD7/USART2_CK/SPI1_MOSI)
NetR222_1: R222.1 U16.122(PD6/USART2_RX/FDCAN2_RXFD_MODE/SPI3_MOSI)
NetR223_1: R223.1 U16.11(PF1/I2C2_SCL)
NetR224_2: R224.2 U4.5 U4.6
NetR229_2: R229.2 U16.103(PA11/TIM1_CH4/SPI2_NSS/UART4_RX/USART1_CTS/FDCAN1_RX)
NetR230_2: R230.2 U16.100(PA8/I2C3_SCL/TIM1_CH1/TIM8_BKIN2/USART1_CK/TIM8_BKIN2_COMP12/UART7_RX)
NetR231_2: R231.2 U16.99(PC9/I2C3_SDA/_TIM3_CH4/TIM8_CH4/UART5_CTS)
NetR302_2: R302.2 U16.82(PD13/TIM4_CH2/I2C4_SDA)
NetR303_2: R303.2 U38.1(EN)
NetR305_2: R305.2 U38.3(CLK)
NetR306_2: R306.2 R307.1 R319.2
NetR307_2: R307.2 U7.5(+)
NetR308_1: R308.1 R352.2 U43.1(Anode)
NetR309_1: R309.1 U16.118(PD4/USART2_RTS/FDCAN1_RXFD_MODE)
NetR310_1: R310.1 U16.117(PD3/SPI2_SCK/USART2_CTS)
NetR311_1: R311.1 U16.116(PD2/_TIM3_ETR/UART5_RX)
NetR312_1: R312.1 U16.115(PD1/UART4_TX/FDCAN1_TX)
NetR318_1: R318.1 R321.2 U7.7
NetR320_2: R320.2 R321.1 U7.6(-)
NetR322_2: R322.2 U16.55(PF15/_I2C4_SDA)
NetR326_2: R326.2 U16.74(PB13/TIM1_CH1N/SPI2_SCK/USART3_CTS/ETH_MII_TXD1/UART5_TX/FDCAN2_TX)
NetR327_2: R327.2 U16.73(PB12/TIM1_BKIN/I2C2_SMBA/SPI2_NSS/USART3_CK/ETH_MII_TXD0/UART5_RX/TIM1_BKIN_COMP12/FDCAN2_RX)
NetR328_2: R328.2 U16.75(PB14/TIM1_CH2N/TIM12_CH1/TIM8_CH2N/USART1_TX/USART3_RTS/UART4_RTS/SPI2_MISO)
NetR329_2: R329.2 U16.76(PB15/TIM1_CH3N/TIM12_CH2/TIM8_CH3N/USART1_RX/_UART4_CTS/SPI2_MOSI)
NetR330_2: R330.2 U39.3
NetR332_2: R332.2 U39.5
NetR334_2: R334.2 U40.5
NetR336_2: R336.2 U39.7
NetR338_2: R338.2 U40.7
NetR350_1: R350.1 R1033.2 U1007.1
NetR351_1: R351.1 R1040.2 U1007.7
NetR1032_2: R1032.2 R1033.1 U1007.2(-)
NetR1039_2: R1039.2 R1040.1 U1007.6(-)
NetTP9_1: TP9.1(TP) U16.139(PB8/TIM16_CH1/TIM4_CH3/I2C1_SCL/I2C4_SCL/UART4_RX/ETH_MII_TXD3/FDCAN1_RX)
NetTP10_1: TP10.1(TP) U16.140(PB9/TIM17_CH1/TIM4_CH4/I2C1_SDA/SPI2_NSS/_I2C4_SDA/I2C4_SMBA/UART4_TX/FDCAN1_TX)
NetTR1_1: TR1.1 U38.6(VD1)
NetTR1_3: TR1.3 U38.4(VD2)

Not connected (* = marked no-connect by the designer): J8 B4; RJ3 9(K1) 10(A1) 11(K2) 12(A2) 15* 16*; U3 7(T2OUT) 9(R2OUT); U16 24(PH1-OSC_OUT); U19 2(NC)* 3(NC)* 5(NC)* 6(NC)* 7(NC)*; U28 1(NC); U40 3 4 13 14; X3 1(NC)*

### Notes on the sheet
- AVDD
- 水温度输入：1~5V
- 水流量输入：1~5V
- 参考电压接的独立3.3V
- 电平未知？
- 外部隔离PWM
- (near R57) 5V/24 快速联锁
- (near R217) 0
- 信号处理板隔离联锁
- (near R15) 0
- (near R218) 0
- 前级驱动联锁
- (near R58) 0
- (near R185) 24V PPS联锁
- (near J9) 开关信号处理班接口
- 外部联锁1
- 24V 状态输出1
- 机柜温度2
- 机柜温度1
- (near TP2) DIN
- 湿度传感器接口
- 电源插件指示灯
- (near J2) 整机面板指示灯
- (near R198) 24V MPS联锁1
- (near R219) 0
- 合成器温度1
- DOUT
- 调试LCD
- 用户外部联锁信号相当于一个开关
- ACDC电源的RS485总线口
- 入水出水温度及流量
- 外部联锁输入1
- (near J12) 激励插件驱动及功放检流
- IO复位，接复位按钮
- 24V 状态输出2
- 预留UART IO
- 外部联锁输出1
- 外部联锁输入2
- (near L1) 湿度传感器
- 电磁阀控制*2
- 外部联锁2
- (near R220) 0
- 三色报警灯*1
- (near R206) 24V MPS联锁2
- 激励插件温度
- Labels drawn without touching a wire or pin: waterflow1, watertemp1

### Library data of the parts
BT1 = Battery: Multicell Battery
C1-C8 C10 C12 C13 C15-C18 C20 C21 C27 C81 C84 C85 C93 C103-C110 C115 C123-C126 C139-C141 C154 C155 C157-C160 C169 C1053 = 0.1uF贴片电容: 贴片电容_GRM188R71H104KA01D_0.1uF±10%,50V,0603; code: 01010045
C9 C11 C55 C138 C142 C171 = 10uF贴片电容: 贴片电容_GRM188R60J106ME47D_10uF±20%,6.3V,0603; code: 01010037
C14 C1054 = 1uF贴片电容: 贴片电容_GRM188R61A105KA61D_1uF±10%,10V,0603; code: 01010038
C19 = 10uF贴片电容: 贴片电容_GRM21BR61A106KE19L_10uF±10%,10V,0805; code: 01010036
C22 = 10uF贴片电容: 0603,2.2UF,50V,±10％,X5R
C23 C24 = 10uF贴片电容: 贴片电容_UMK107BBJ225KA-T_2.2uF±110%,50V,0603; MPN: Taiyo Yuden; code: 01010198
C80 = 10uF贴片电容: 贴片电容_GRM32ER71H106KA12L_10uF±10%,50V,1210; code: 03030021
C94 = 0.1uF: GRM188R71H104KA01D; MPN: MURATA; WSPN: 01010045
C111 = 4.7UF: 0603,4.7UF,16V,±10％,X5R; 名称: 贴片电容; 代码: 1.01.01.026; 规格型号: GRM188R61C475K; 品牌: Murata（村田）
C112 = 1UF: 0603,1UF,10V,±10％,X5R; 代码: 1.01.01.012; 名称: 贴片电容; 规格型号: GRM188R61A105KA61D; 品牌: Murata（村田）
C122 C127 = 0.1uF贴片电容: code: 01010045
C1061 C1068 = 100pF贴片电容: 贴片电容_GRM185C1H101K_100pF±10%,50V,0603; code: 01010095
D2 D20 D33 = ESD5B5.0ST1G
D3-D12 D16 D21 D22 D27-D32 D35-D41 D43-D45 D47 D56-D58 D68 D69 D71-D74 = ESD5B5.0ST1G: ESD_ESD3V3D3B_SOD-323,3.3V,双管
D13 = SM712: ESD_ESD15VAPB_SOT23
D14 D15 = ESD5B5.0ST1G: TVS_ESD5B5.0ST1G_SOD-523
D17 = SM712: ESD_ESDSM712_SOT23
D18 D42 D54 D55 D65 = ESD5B5.0ST1G: ESD_ESD5V0D3B_SOD-323,5V,双管
D19 D34 D46 D48-D51 D59 D66 D67 D70 = SMBJ12CA: TVS_SMBJ24CA_SMB封装
D52 D62 D63 = B0540WS: 二极管_SOD323
D53 = BAT54CW: TVS_BAT54CW_SOT323
F1 F2 = 自恢复保险丝_SMD020-1206
FB2 FB3 FB8 FB10 FB11 FB18 FB19 FB21-FB24 FB33 L1 = 0805贴片磁珠: 贴片磁珠_600R,0805; code: 01030023
FB4 FB5 FB7 FB9 FB16 FB17 FB20 FB36 FB1007 = 0603贴片磁珠: 贴片磁珠_100R,0603; code: 0103016
FB34 FB35 = 0603贴片磁珠: code: 0103016
J1 = 8p-2.54单排母座: 连接器_单排排母座8p_直插,间距2.54mm; MPN: WS; code: 01090052
J2 J4 J9 J12 = DB9-90度弯针: 连接器_DB9母头_90度弯针; code: 0207003
J3 J5 J6 J8 = 双胞胎DB9DB9母头: 连接器_双胞胎DB9DB9母头_90度弯针，间距15.88mm; MPN: 亚当科技; code: 0207011
Q2 Q6-Q9 Q12-Q15 = MMBT2222: NPN三极管_MMBT2222_表贴SOT23; code: 01050001
R1-R7 R15 R17 R51 R58 R89 R120 R121 R153 R172 R217-R220 R228 R303 R317 R325 = 4.7K贴片电阻: 贴片电阻_4.7K±5%,0603; code: 01020012
R8 R10 R21 R225 = 1K贴片电阻: 贴片电阻_1K±5%,0603; code: 01020082
R9 R53 R55 R103 R144 R146 R158 R161 R224 R313 R314 R320 R321 R1026 R1038 = 0Ω贴片电阻: 贴片电阻_0Ω±5%,0603; code: 01020010
R11-R14 R36 R41 R49 R52 R57 R127-R129 R152 R176 R182 R185 R187 R198-R200 R202 R203 R205-R207 R209-R212 R221 R222 R309-R312 = 0Ω贴片电阻: code: 01020010
R16 R39 R40 R46 R105 R190 R315 R316 R340-R352 = 510Ω贴片电阻: 贴片电阻_510Ω±5%,0603; code: 01020103
R18 R33 R34 R38 R44 R331 R333 R335 R337 R339 = 1.5K贴片电阻: 贴片电阻_4.7K±5%,0603; code: 01020012
R19 R20 R23-R27 R29 R30 R32 R35 R42 R43 R45 R47 R56 R59 R90-R98 R100 R106 R107 R111 R113 R115 R116 R119 R123 R141 R142 R151 R167-R171 R173-R175 R177 R178 R208 R213-R215 R223 R229-R231 R302 R318 R322 R326-R329 = 30Ω贴片电阻: 贴片电阻_30Ω±5%,0603; code: 01020108
R22 R162 R165 = 300Ω贴片电阻: 贴片电阻_300Ω±5%,0603; code: 01020008
R31 R37 R188 R192 R323 R324 R330 R332 R334 R336 R338 = 33K贴片电阻: code: 01020011
R50 R183 R184 R189 R191 R193 R194 R201 R204 R227 R308 = 3K贴片电阻: 贴片电阻_3K±5%,1206; code: 01020048
R104 = 10Ω贴片电阻: 贴片电阻_10Ω±5%,0603; code: 01020104
R149 R306 = 1K贴片电阻
R150 R307 = 300Ω贴片电阻: 0603,100Ω,±5％; code: 01020008
R154 R197 R319 = 1K贴片电阻: code: 01020082
R186 = 120Ω贴片电阻: 贴片电阻_120Ω±5%,0603; code: 01020112
R216 = 1.5K贴片电阻: 贴片电阻_1.5K±5%,0603; code: 01020063
R226 = 6.2K贴片电阻: 贴片电阻_1K±5%,0603; code: 01020106
R304 = 4.7KΩ: 0603,4.7KΩ,±1％; 名称: 贴片电阻; 代码: 1.02.01.067; 规格型号: RC0603FR-074K7L; 品牌: YAGEO
R305 = 51KΩ: 0603,51KΩ,±1%; 名称: 贴片电阻
R1032 R1039 = 1K贴片电阻: 贴片电阻_1K±1%,0603; code: 01020082
R1033 R1040 = 4.7K贴片电阻: 贴片电阻_2K±1%,0603
RJ3 = RJ45弯脚带灯: RJ45插座_1*1,带左黄右绿灯,弯脚; MPN: 朱迅; code: 01090042
TP2 TP9 TP10 = TP0.8mm: 表贴测试点0.8mm
TR1 = VPT85BB-01A: 推挽变压器_表贴,隔离电压1500VDC
U1 = AT24C02N: EEPROM_AT24C02N_SOIC8; Maker: ATMEL; code: 01060068
U3 = MAX3232CSE: 双通道232收发器_MAX3232CSE_SOIC16; Maker: Maxim; code: 01060032
U4 = G5V-1-5VDC: 继电器_G5V-1-5VDC; MPN: OMRON; code: 01060120
U5 = SN65LBC184DR: 差分收发器_SN65LBC184DR_SOIC8; Maker: TI; code: 01060058
U6 = W25Q64CVSSIG: SPI存储芯片_W25Q64CVSSIG_SOIC8; MPN: WINBOND; code: 01060109
U7 = LM358
U8 U12 U14 U25 U41-U43 = TLP2368: 高速光耦合器_SO6封装,2.7~5.5V,3750Vrms
U11 U13 U15 = TLP181: 光耦_TLP181
U16 = STM32H743ZI: LQFP144,32-bit Arm, 480MHz MCUs, 2MB Flash,  1 MB RAM, analog interfaces, crypto
U19 = DS18B20U: 温度传感器_DS18B20U_uSOP8; code: 01060045
U23 = SN74HC4075DR: 3路或门_SN74HC4075_SOIC14; Maker: TI; code: 01060030
U28 = SN74AHC1G04DC: 单路非门_SN74AHC1G04DC_SC70-5; code: 010600100
U29 = Si2369DS-T1-GE3: P-MOS_Si2369DS-T1-GE3_SOT23; code: 01060087
U36 = ADuM1201A: 双通道数字隔离器_ADuM1201A_SOIC8; Maker: ADI
U38 = VPS8504: 推挽式变压器驱动器_SOT23-6,输入2.8~6V
U39 U40 = TLP291-4: 光耦_TLP181
U1007 = LM358: 运算放大器_LM358_SOIC8; Maker: MOTOROLA; code: 01060025
X3 = 16M贴片有源晶振: 贴片有源晶振_40M,20ppm,封装5x7; MPN: KDS; code: 03050020

## Sheet 2-RJ45.SchDoc
size A3
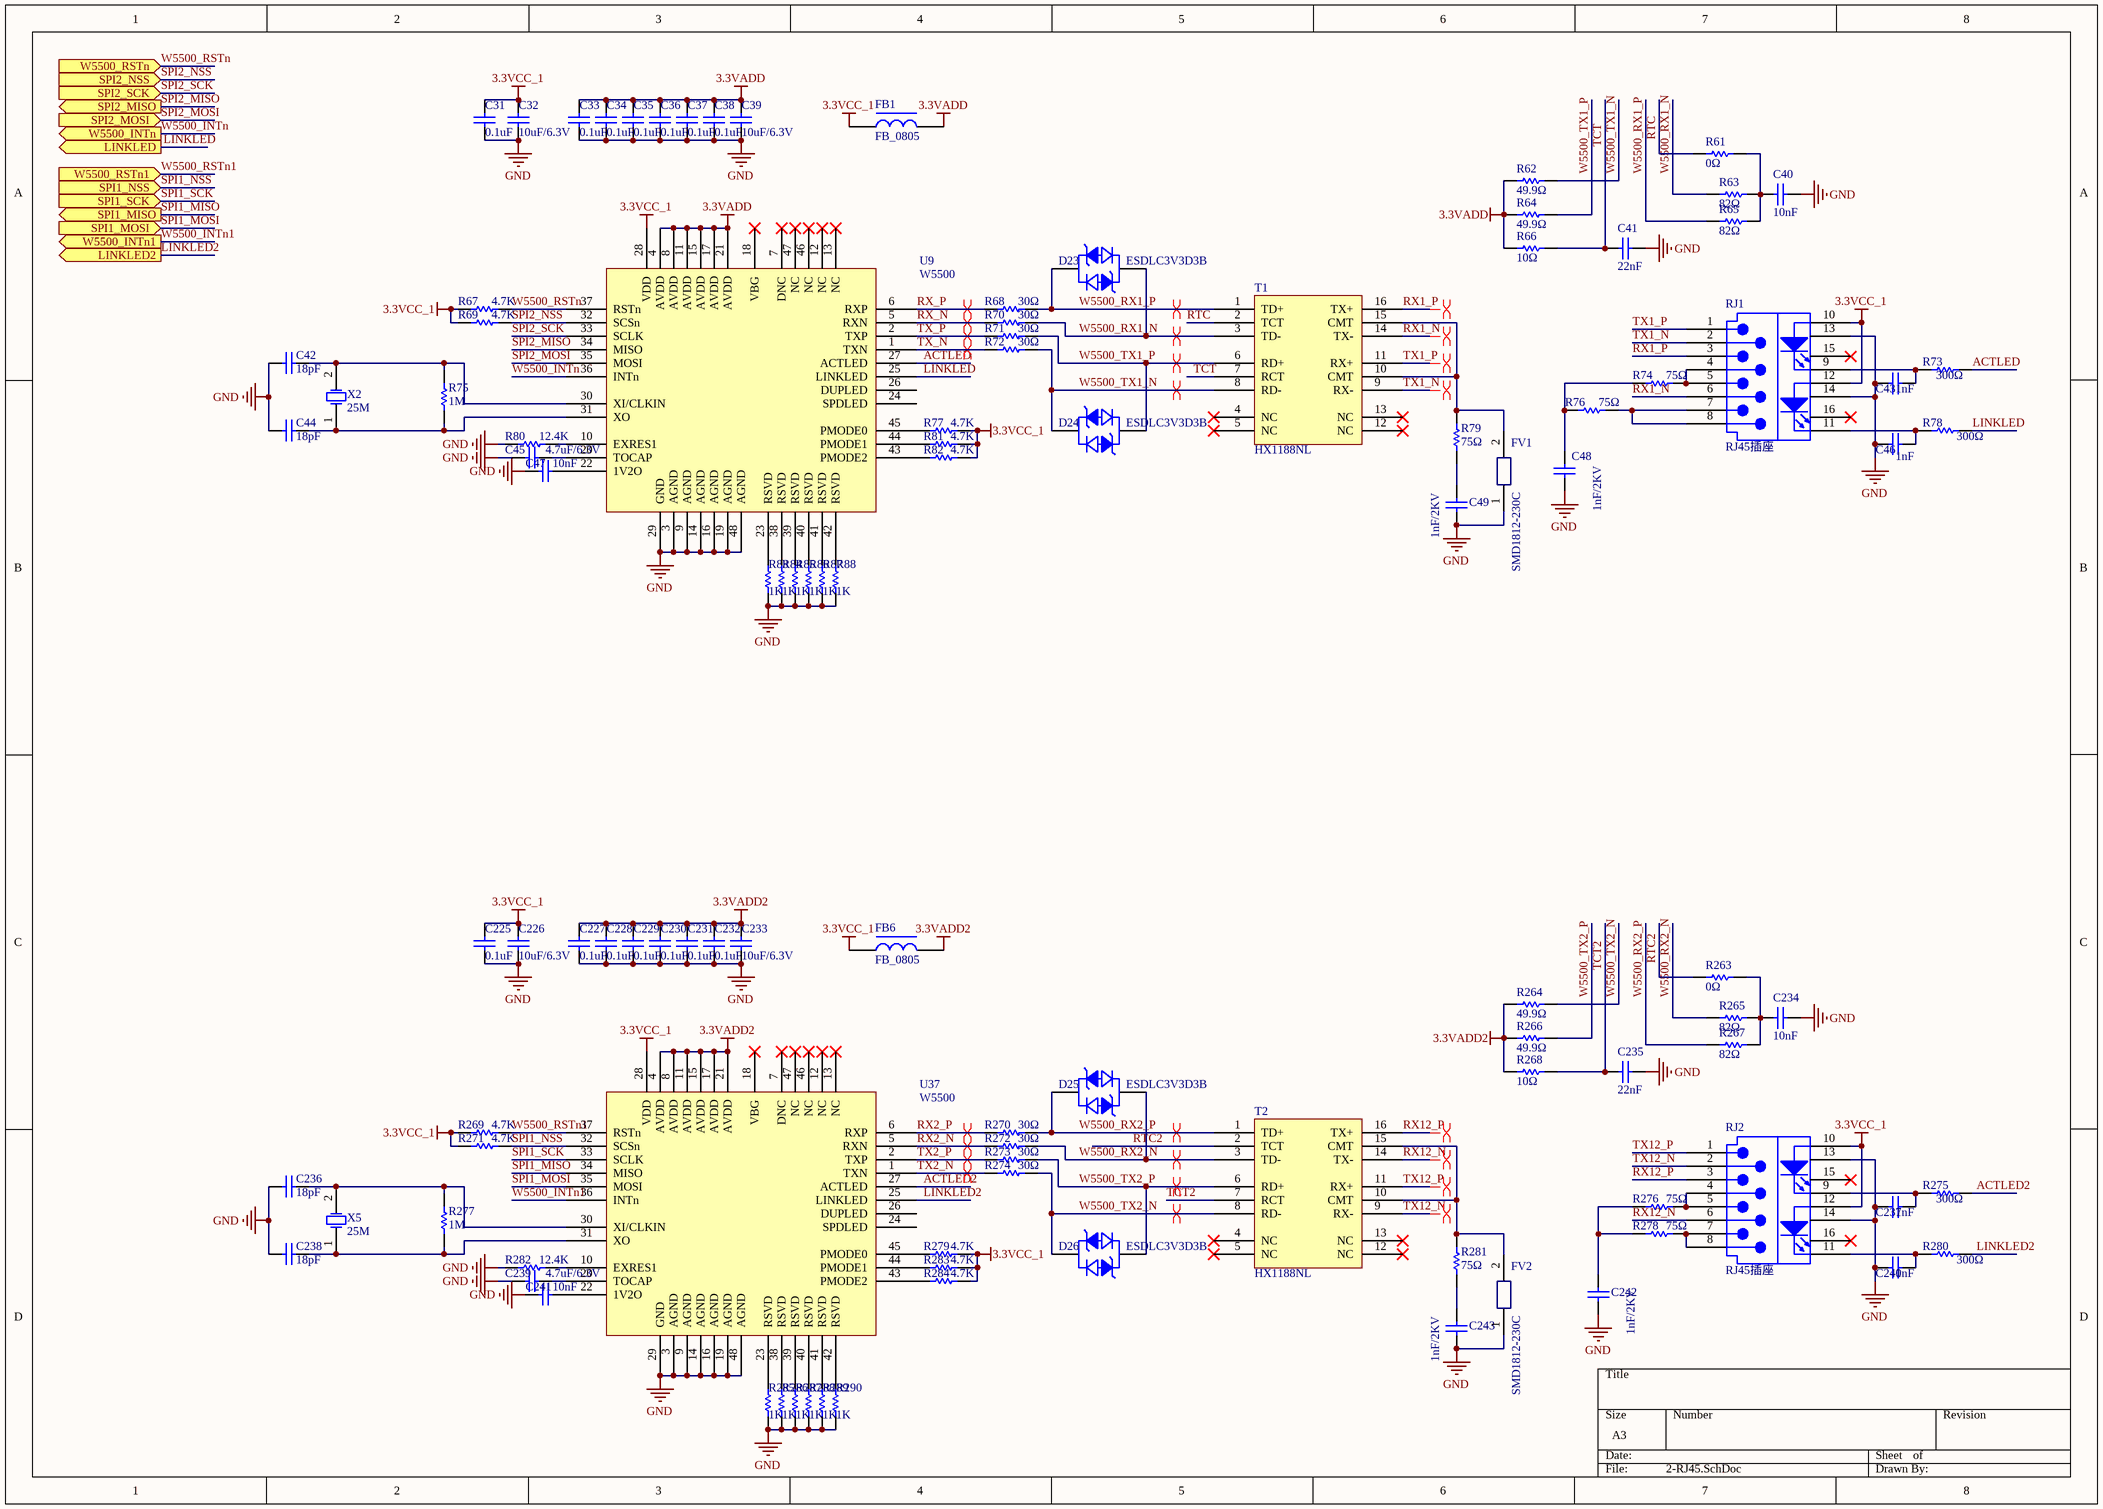
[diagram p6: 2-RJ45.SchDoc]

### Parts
C31  0.1uF  [C0603]
C32  10uF/6.3V  [C0603]
C33  0.1uF  [C0603]
C34  0.1uF  [C0603]
C35  0.1uF  [C0603]
C36  0.1uF  [C0603]
C37  0.1uF  [C0603]
C38  0.1uF  [C0603]
C39  10uF/6.3V  [C0603]
C40  10nF  [C0603]
C41  22nF  [C0603]
C42  18pF  [C0603]
C43  1nF  [C0603]
C44  18pF  [C0603]
C45  4.7uF/6.3V  [C0603]
C46  1nF  [C0603]
C47  10nF  [C0603]
C48  1nF/2KV  [C1206]
C49  1nF/2KV  [C1206]
C225  0.1uF  [C0603]
C226  10uF/6.3V  [C0603]
C227  0.1uF  [C0603]
C228  0.1uF  [C0603]
C229  0.1uF  [C0603]
C230  0.1uF  [C0603]
C231  0.1uF  [C0603]
C232  0.1uF  [C0603]
C233  10uF/6.3V  [C0603]
C234  10nF  [C0603]
C235  22nF  [C0603]
C236  18pF  [C0603]
C237  1nF  [C0603]
C238  18pF  [C0603]
C239  4.7uF/6.3V  [C0603]
C240  1nF  [C0603]
C241  10nF  [C0603]
C242  1nF/2KV  [C1206]
C243  1nF/2KV  [C1206]
D23  ESDLC3V3D3B  [SOD-323]
D24  ESDLC3V3D3B  [SOD-323]
D25  ESDLC3V3D3B  [SOD-323]
D26  ESDLC3V3D3B  [SOD-323]
FB1  FB_0805  [L0805]
FB6  FB_0805  [L0805]
FV1  SMD1812-230C  [D1812]
FV2  SMD1812-230C  [D1812]
R61  0Ω  [R0603]
R62  49.9Ω  [R0603]
R63  82Ω  [R0603]
R64  49.9Ω  [R0603]
R65  82Ω  [R0603]
R66  10Ω  [R0603]
R67  4.7K  [R0603]
R68  30Ω  [R0603]
R69  4.7K  [R0603]
R70  30Ω  [R0603]
R71  30Ω  [R0603]
R72  30Ω  [R0603]
R73  300Ω  [R0603]
R74  75Ω  [R0805]
R75  1M  [R0603]
R76  75Ω  [R0805]
R77  4.7K  [R0603]
R78  300Ω  [R0603]
R79  75Ω  [R1206]
R80  12.4K  [R0603]
R81  4.7K  [R0603]
R82  4.7K  [R0603]
R83  1K  [R0603]
R84  1K  [R0603]
R85  1K  [R0603]
R86  1K  [R0603]
R87  1K  [R0603]
R88  1K  [R0603]
R263  0Ω  [R0603]
R264  49.9Ω  [R0603]
R265  82Ω  [R0603]
R266  49.9Ω  [R0603]
R267  82Ω  [R0603]
R268  10Ω  [R0603]
R269  4.7K  [R0603]
R270  30Ω  [R0603]
R271  4.7K  [R0603]
R272  30Ω  [R0603]
R273  30Ω  [R0603]
R274  30Ω  [R0603]
R275  300Ω  [R0603]
R276  75Ω  [R0805]
R277  1M  [R0603]
R278  75Ω  [R0805]
R279  4.7K  [R0603]
R280  300Ω  [R0603]
R281  75Ω  [R1206]
R282  12.4K  [R0603]
R283  4.7K  [R0603]
R284  4.7K  [R0603]
R285  1K  [R0603]
R286  1K  [R0603]
R287  1K  [R0603]
R288  1K  [R0603]
R289  1K  [R0603]
R290  1K  [R0603]
RJ1  RJ45插座  [RJ45TH-1x1-2R54-LED]
RJ2  RJ45插座  [RJ45TH-1x1-2R54-LED]
T1  HX1188NL  [SOP16-1R27-7R11x12R7]
T2  HX1188NL  [SOP16-1R27-7R11x12R7]
U9  W5500  [TQFN48-0R5-7X7]
U37  W5500  [TQFN48-0R5-7X7]
X2  25M  [CRY2SM-6R0x3R5]
X5  25M  [CRY2SM-6R0x3R5]

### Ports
LINKLED2 (out), LINKLED (out), SPI1_MISO (out), SPI1_MOSI (in), SPI1_NSS (in), SPI1_SCK (in), SPI2_MISO (out), SPI2_MOSI (in), SPI2_NSS (in), SPI2_SCK (in), W5500_INTn1 (out), W5500_INTn (out), W5500_RSTn1 (in), W5500_RSTn (in)

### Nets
3.3VADD: C33.2 C34.2 C35.2 C36.2 C37.2 C38.2 C39.2 FB1.2 R62.2 R64.2 R66.2 U9.4(AVDD) U9.8(AVDD) U9.11(AVDD) U9.15(AVDD) U9.17(AVDD) U9.21(AVDD)
3.3VADD2: C227.2 C228.2 C229.2 C230.2 C231.2 C232.2 C233.2 FB6.2 R264.2 R266.2 R268.2 U37.4(AVDD) U37.8(AVDD) U37.11(AVDD) U37.15(AVDD) U37.17(AVDD) U37.21(AVDD)
3.3VCC_1: C31.2 C32.2 C225.2 C226.2 FB1.1 FB6.1 R67.2 R69.2 R77.2 R81.2 R82.2 R269.2 R271.2 R279.2 R283.2 R284.2 RJ1.10(A1) RJ1.12(A2) RJ2.10(A1) RJ2.12(A2) U9.28(VDD) U37.28(VDD)
GND: C31.1 C32.1 C33.1 C34.1 C35.1 C36.1 C37.1 C38.1 C39.1 C40.1 C41.1 C42.1 C43.1 C44.1 C45.1 C46.1 C47.2 C48.1 C49.1 C225.1 C226.1 C227.1 C228.1 C229.1 C230.1 C231.1 C232.1 C233.1 C234.1 C235.1 C236.1 C237.1 C238.1 C239.1 C240.1 C241.2 C242.1 C243.1 FV1.1 FV2.1 R80.1 R83.1 R84.1 R85.1 R86.1 R87.1 R88.1 R282.1 R285.1 R286.1 R287.1 R288.1 R289.1 R290.1 RJ1.13 RJ1.14 RJ2.13 RJ2.14 U9.3(AGND) U9.9(AGND) U9.14(AGND) U9.16(AGND) U9.19(AGND) U9.29(GND) U9.48(AGND) U37.3(AGND) U37.9(AGND) U37.14(AGND) U37.16(AGND) U37.19(AGND) U37.29(GND) U37.48(AGND)
ACTLED: R73.2 U9.27(ACTLED)
ACTLED2: R275.2 U37.27(ACTLED)
LINKLED: R78.2 U9.25(LINKLED) ; port LINKLED
LINKLED2: R280.2 U37.25(LINKLED) ; port LINKLED2
RTC: R61.2 T1.2(TCT)
RTC2: R263.2 T2.2(TCT)
RX1_N: RJ1.6(RX-) T1.14(TX-)
RX1_P: RJ1.3(RX+) T1.16(TX+)
RX2_N: R272.1 U37.5(RXN)
RX2_P: R270.1 U37.6(RXP)
RX12_N: RJ2.6(RX-) T2.14(TX-)
RX12_P: RJ2.3(RX+) T2.16(TX+)
RX_N: R70.1 U9.5(RXN)
RX_P: R68.1 U9.6(RXP)
SPI1_MISO: U37.34(MISO) ; port SPI1_MISO
SPI1_MOSI: U37.35(MOSI) ; port SPI1_MOSI
SPI1_NSS: R271.1 U37.32(SCSn) ; port SPI1_NSS
SPI1_SCK: U37.33(SCLK) ; port SPI1_SCK
SPI2_MISO: U9.34(MISO) ; port SPI2_MISO
SPI2_MOSI: U9.35(MOSI) ; port SPI2_MOSI
SPI2_NSS: R69.1 U9.32(SCSn) ; port SPI2_NSS
SPI2_SCK: U9.33(SCLK) ; port SPI2_SCK
TCT: C41.2 R66.1 T1.7(RCT)
TCT2: C235.2 R268.1 T2.7(RCT)
TX1_N: RJ1.2(TX-) T1.9(RX-)
TX1_P: RJ1.1(TX+) T1.11(RX+)
TX2_N: R274.1 U37.1(TXN)
TX2_P: R273.1 U37.2(TXP)
TX12_N: RJ2.2(TX-) T2.9(RX-)
TX12_P: RJ2.1(TX+) T2.11(RX+)
TX_N: R72.1 U9.1(TXN)
TX_P: R71.1 U9.2(TXP)
W5500_INTn: U9.36(INTn) ; port W5500_INTn
W5500_INTn1: U37.36(INTn) ; port W5500_INTn1
W5500_RSTn: R67.1 U9.37(RSTn) ; port W5500_RSTn
W5500_RSTn1: R269.1 U37.37(RSTn) ; port W5500_RSTn1
W5500_RX1_N: D23.2 R63.2 R70.2 T1.3(TD-)
W5500_RX1_P: D23.1 R65.2 R68.2 T1.1(TD+)
W5500_RX2_N: D25.2 R265.2 R272.2 T2.3(TD-)
W5500_RX2_P: D25.1 R267.2 R270.2 T2.1(TD+)
W5500_TX1_N: D24.1 R62.1 R72.2 T1.8(RD-)
W5500_TX1_P: D24.2 R64.1 R71.2 T1.6(RD+)
W5500_TX2_N: D26.1 R264.1 R274.2 T2.8(RD-)
W5500_TX2_P: D26.2 R266.1 R273.2 T2.6(RD+)
NetC40_2: C40.2 R61.1 R63.1 R65.1
NetC42_2: C42.2 R75.2 U9.30(XI/CLKIN) X2.2(OSC2)
NetC43_2: C43.2 R73.1 RJ1.9(K1)
NetC44_2: C44.2 R75.1 U9.31(XO) X2.1(OSC1)
NetC45_2: C45.2 U9.20(TOCAP)
NetC46_2: C46.2 R78.1 RJ1.11(K2)
NetC47_1: C47.1 U9.22(1V2O)
NetC48_2: C48.2 R74.1 R76.1
NetC49_2: C49.2 R79.1
NetC234_2: C234.2 R263.1 R265.1 R267.1
NetC236_2: C236.2 R277.2 U37.30(XI/CLKIN) X5.2(OSC2)
NetC237_2: C237.2 R275.1 RJ2.9(K1)
NetC238_2: C238.2 R277.1 U37.31(XO) X5.1(OSC1)
NetC239_2: C239.2 U37.20(TOCAP)
NetC240_2: C240.2 R280.1 RJ2.11(K2)
NetC241_1: C241.1 U37.22(1V2O)
NetC242_2: C242.2 R276.1 R278.1
NetC243_2: C243.2 R281.1
NetFV1_2: FV1.2 R79.2 T1.10(CMT) T1.15(CMT)
NetFV2_2: FV2.2 R281.2 T2.10(CMT) T2.15(CMT)
NetR74_2: R74.2 RJ1.4(NC) RJ1.5(NC)
NetR76_2: R76.2 RJ1.7(NC) RJ1.8(NC)
NetR77_1: R77.1 U9.45(PMODE0)
NetR80_2: R80.2 U9.10(EXRES1)
NetR81_1: R81.1 U9.44(PMODE1)
NetR82_1: R82.1 U9.43(PMODE2)
NetR83_2: R83.2 U9.23(RSVD)
NetR84_2: R84.2 U9.38(RSVD)
NetR85_2: R85.2 U9.39(RSVD)
NetR86_2: R86.2 U9.40(RSVD)
NetR87_2: R87.2 U9.41(RSVD)
NetR88_2: R88.2 U9.42(RSVD)
NetR276_2: R276.2 RJ2.4(NC) RJ2.5(NC)
NetR278_2: R278.2 RJ2.7(NC) RJ2.8(NC)
NetR279_1: R279.1 U37.45(PMODE0)
NetR282_2: R282.2 U37.10(EXRES1)
NetR283_1: R283.1 U37.44(PMODE1)
NetR284_1: R284.1 U37.43(PMODE2)
NetR285_2: R285.2 U37.23(RSVD)
NetR286_2: R286.2 U37.38(RSVD)
NetR287_2: R287.2 U37.39(RSVD)
NetR288_2: R288.2 U37.40(RSVD)
NetR289_2: R289.2 U37.41(RSVD)
NetR290_2: R290.2 U37.42(RSVD)

Not connected (* = marked no-connect by the designer): RJ1 15* 16*; RJ2 15* 16*; T1 4(NC)* 5(NC)* 12(NC)* 13(NC)*; T2 4(NC)* 5(NC)* 12(NC)* 13(NC)*; U9 7(DNC)* 12(NC)* 13(NC)* 18(VBG)* 24(SPDLED) 26(DUPLED) 46(NC)* 47(NC)*; U37 7(DNC)* 12(NC)* 13(NC)* 18(VBG)* 24(SPDLED) 26(DUPLED) 46(NC)* 47(NC)*

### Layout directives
differential pair: RX1_N, RX1_P, RX2_N, RX2_P, RX12_N, RX12_P, RX_N, RX_P, TX1_N, TX1_P, TX2_N, TX2_P, TX12_N, TX12_P, TX_N, TX_P, W5500_RX1_N, W5500_RX1_P, W5500_RX2_N, W5500_RX2_P, W5500_TX1_N, W5500_TX1_P, W5500_TX2_N, W5500_TX2_P

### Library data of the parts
C31 C33-C38 C225 C227-C232 = 0.1uF贴片电容: as C1 on sheet 1-MCU
C32 C39 C226 C233 = 10uF贴片电容: as C9 on sheet 1-MCU
C40 C47 C234 C241 = 0.1uF贴片电容: C0603C103K5RAC_10nF±10%,50V,0603; MPN: KEMET; code: 01010218
C41 C235 = 27nF贴片电容: 贴片电容_22nF±5%,50V,0603; code: 01010054
C42 C44 C236 C238 = 18pF贴片电容: 贴片电容_GRM1885C1H180JA01D_18pF±5%,50V,0603; code: 01010102
C43 C46 C237 C240 = 1000pF贴片电容: 贴片电容_GRM188R71H102KA01_1000pF±10%,50V,0603; code: 01010093
C45 C239 = 1uF贴片电容: GRM188R61C475K_4.7uF±10%,16V,0603; MPN: Murata; code: 01010098
C48 C49 = 10uF贴片电容: 贴片电容_1206B102K202NT_1206,1000PF/2KV; MPN: 风华; code: 01010100
C242 C243 = 10uF贴片电容: 贴片电容_1000pF/2KV
D23-D26 = ESDLC3V3D3B: ESD_ESDLC3V3D3B _SOD-323封装
FB1 FB6 = 0805贴片磁珠: 贴片磁珠_600R,0805; code: 01030023
FV1 FV2 = 4532-401-LF: 贴片陶瓷气体放电管_SMD1812-230C_1812,230V,2KA; MPN: Littelfuse; code: 01070013
R61 R263 = 0Ω贴片电阻: 贴片电阻_0Ω±5%,0603; code: 01020010
R62 R64 R264 R266 = 51Ω贴片电阻: 贴片电阻_49.9Ω±1%,0603; code: 01020126
R63 R65 R265 R267 = 51Ω贴片电阻: 贴片电阻_82Ω±1%,0603; code: 01020196
R66 R268 = 10Ω贴片电阻: 贴片电阻_10Ω±5%,0603; code: 01020104
R67 R69 R77 R81 R82 R269 R271 R279 R283 R284 = 4.7K贴片电阻: 贴片电阻_4.7K±5%,0603; code: 01020012
R68 R70-R72 R270 R272-R274 = 30Ω贴片电阻: 贴片电阻_30Ω±5%,0603; code: 01020108
R73 R78 R275 R280 = 300Ω贴片电阻: 贴片电阻_300Ω±5%,0603; code: 01020008
R74 R76 R276 R278 = 75Ω贴片电阻: 贴片电阻_75Ω±5%,0805; code: 01020068
R75 R277 = 1M贴片电阻: 贴片电阻_1M±5%,0603; code: 01020093
R79 R281 = 75Ω贴片电阻: 贴片电阻_75Ω±5%,1206; code: 01020197
R80 R282 = 12K贴片电阻: 贴片电阻_12.4K±1%,0603
R83-R88 R285-R290 = 1K贴片电阻: 贴片电阻_1K±5%,0603; code: 01020082
RJ1 RJ2 = RJ45弯脚带灯: as RJ3 on sheet 1-MCU
T1 T2 = HX1188NL: 网络变压器_HX1188NL_百兆,SOIC16; code: 01060114
U9 U37 = W5500: 以太网控制器_W5500_LQFP48; code: 01060113
X2 = 25M贴片无源晶体: 贴片无源晶体_25MHz,30ppm,6035封装; code: 03050012
X5 = 8M贴片无源晶体: 贴片无源晶体_25MHz,封装6035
